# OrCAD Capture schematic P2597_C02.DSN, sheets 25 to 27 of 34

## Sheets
25 09_PCIe x4 Connector: size Custom
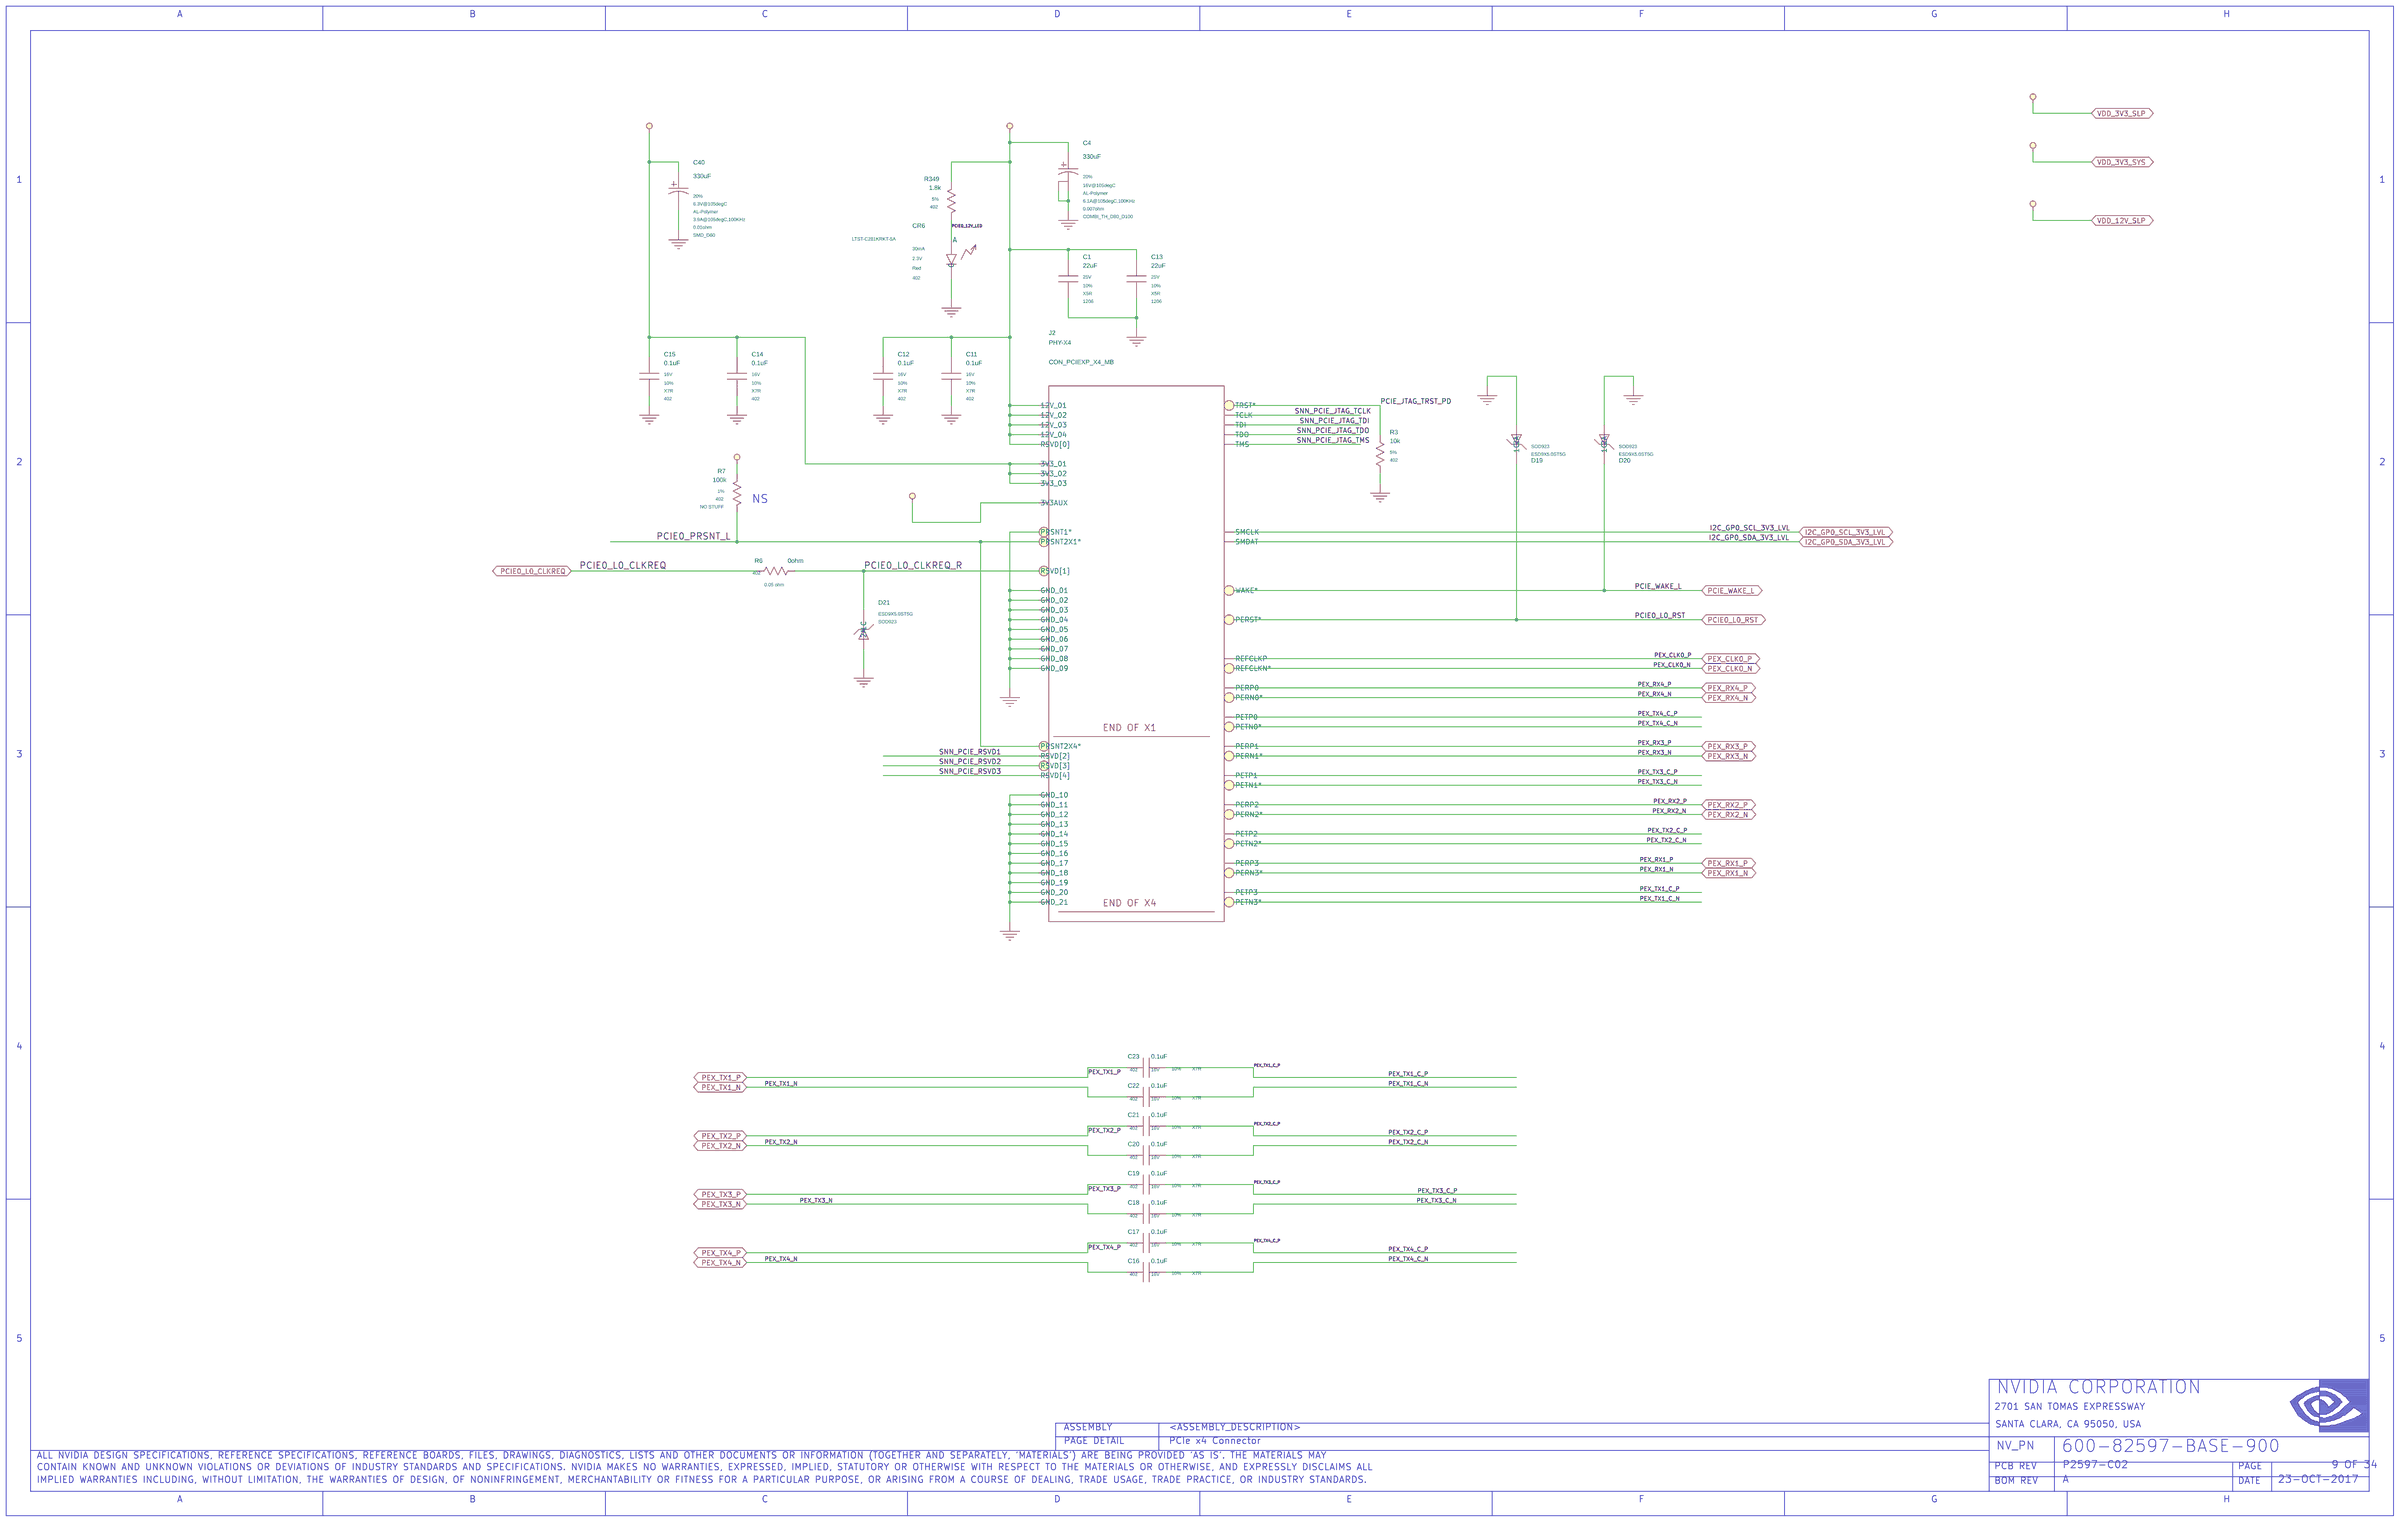
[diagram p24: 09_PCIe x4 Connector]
26 08_USB3.0 type A and USB2.0 m: size Custom
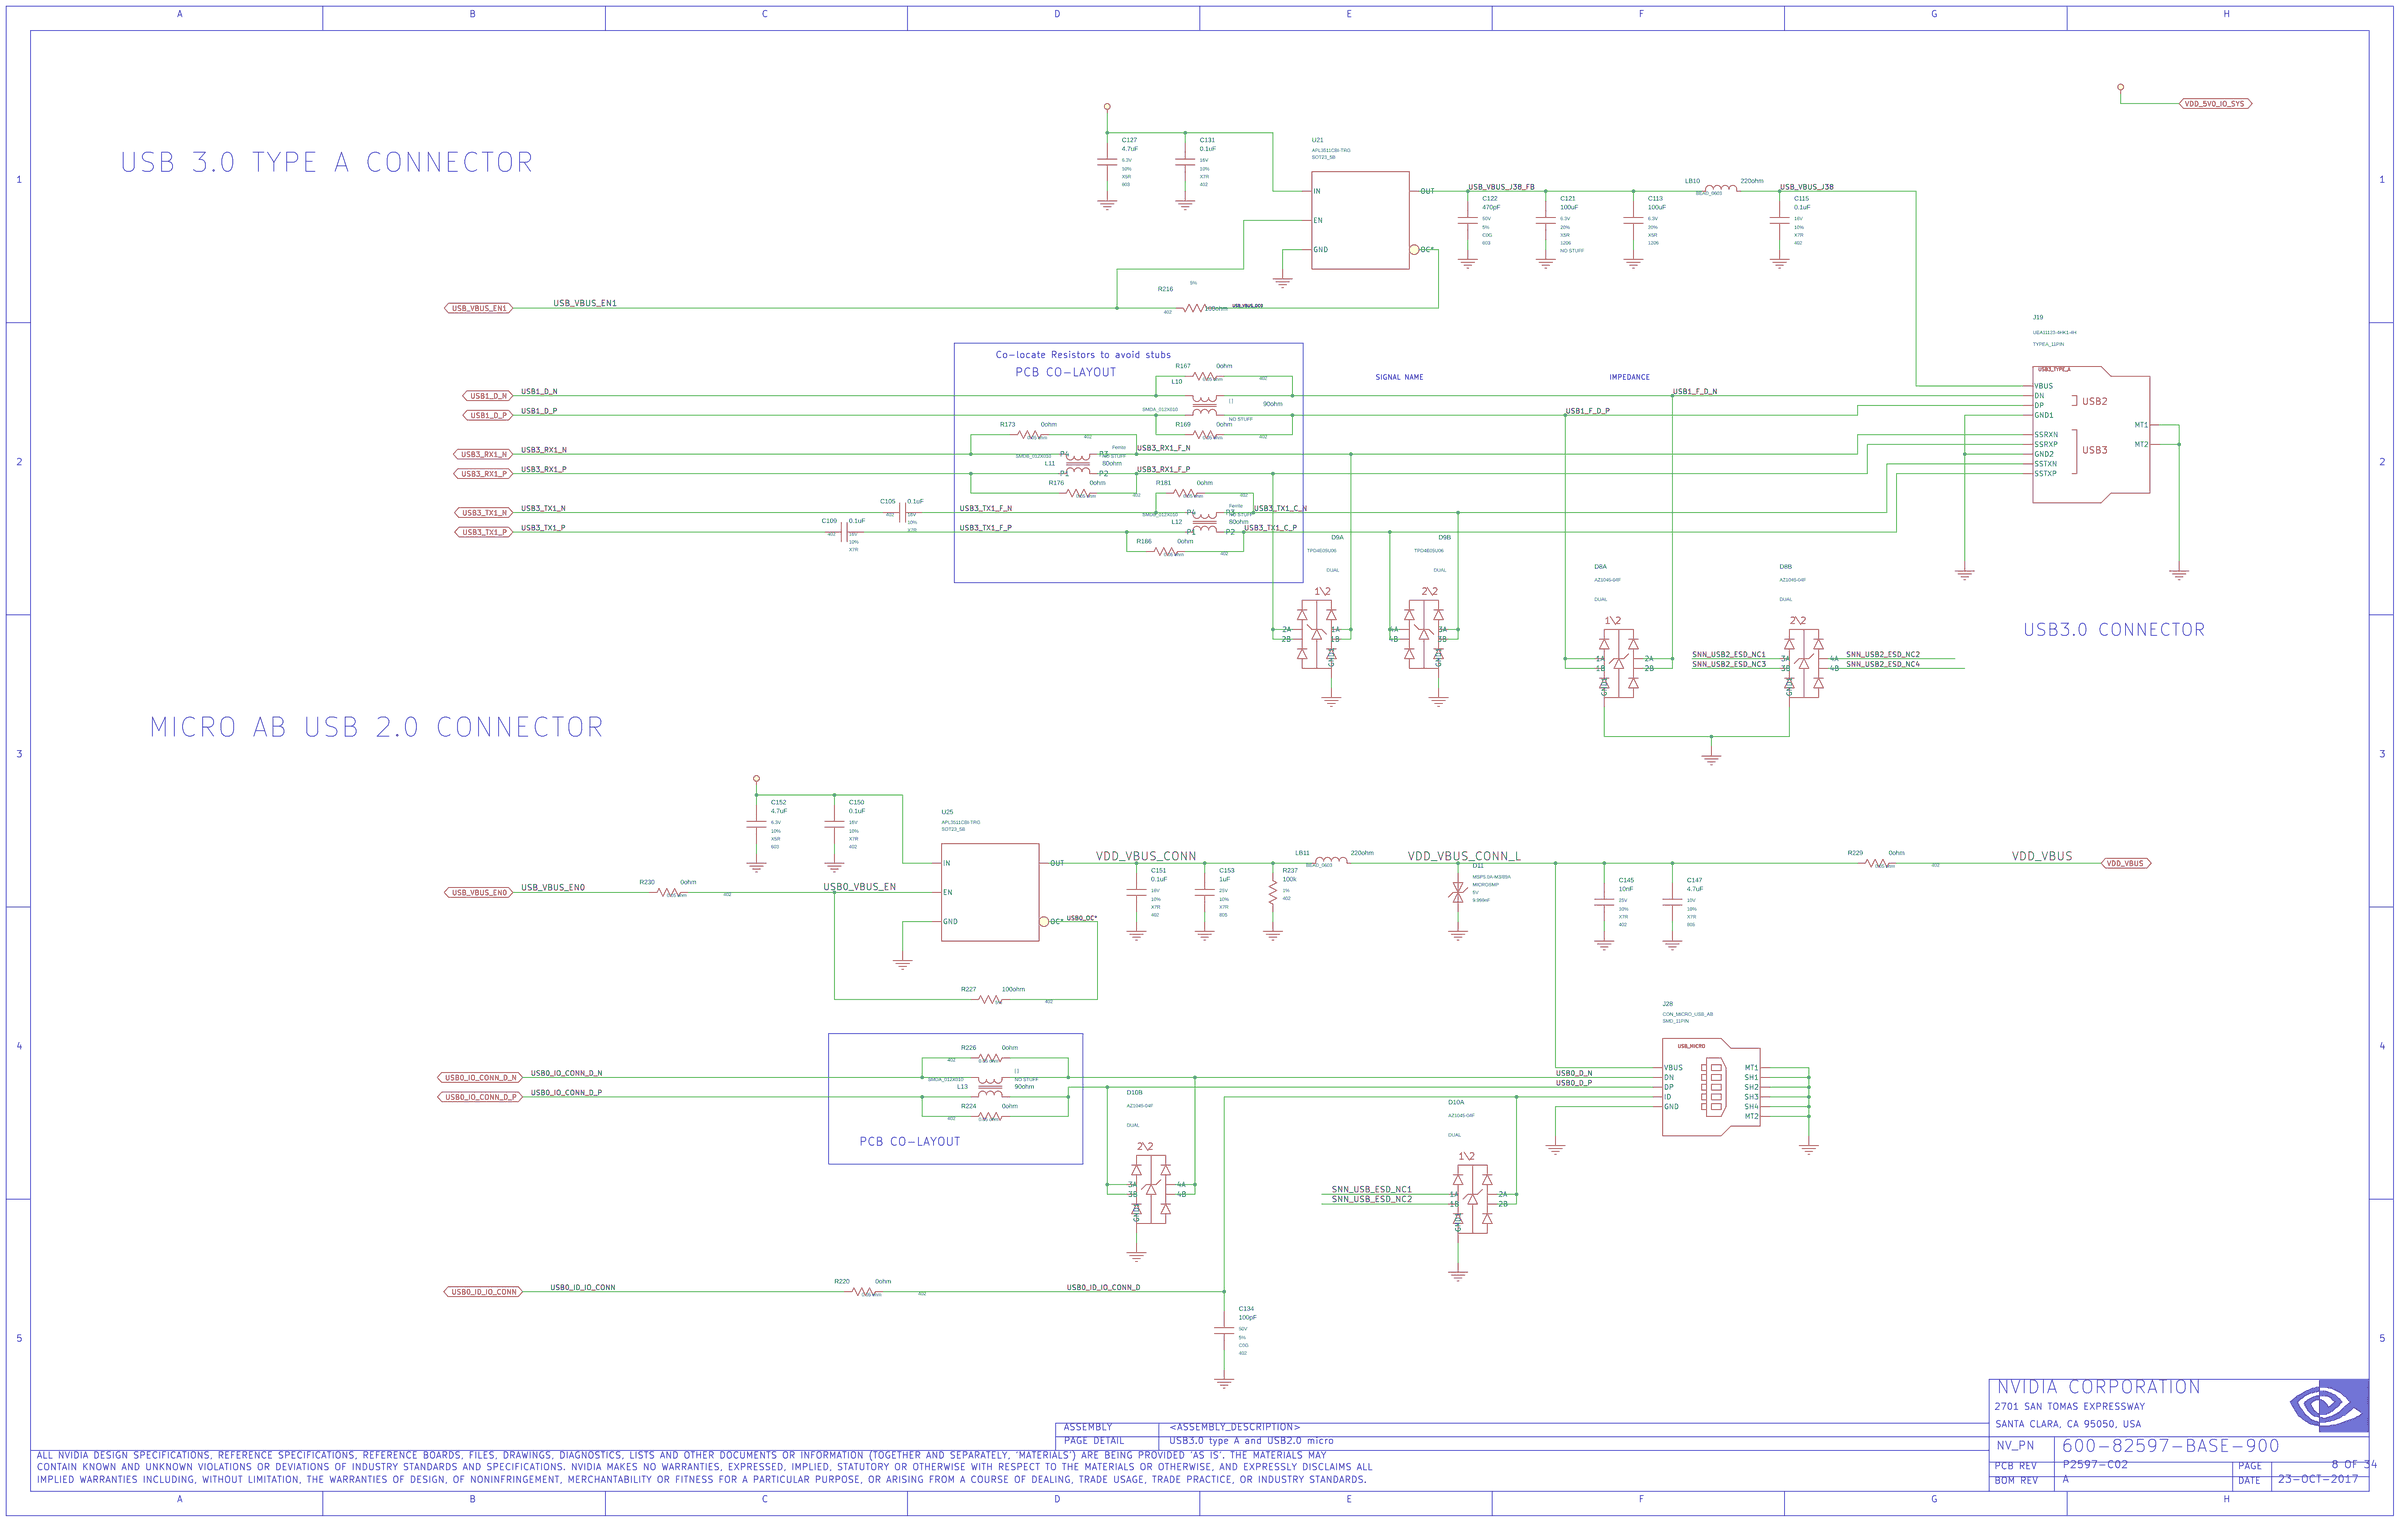
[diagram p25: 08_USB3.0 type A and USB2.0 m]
27 07_BLANK
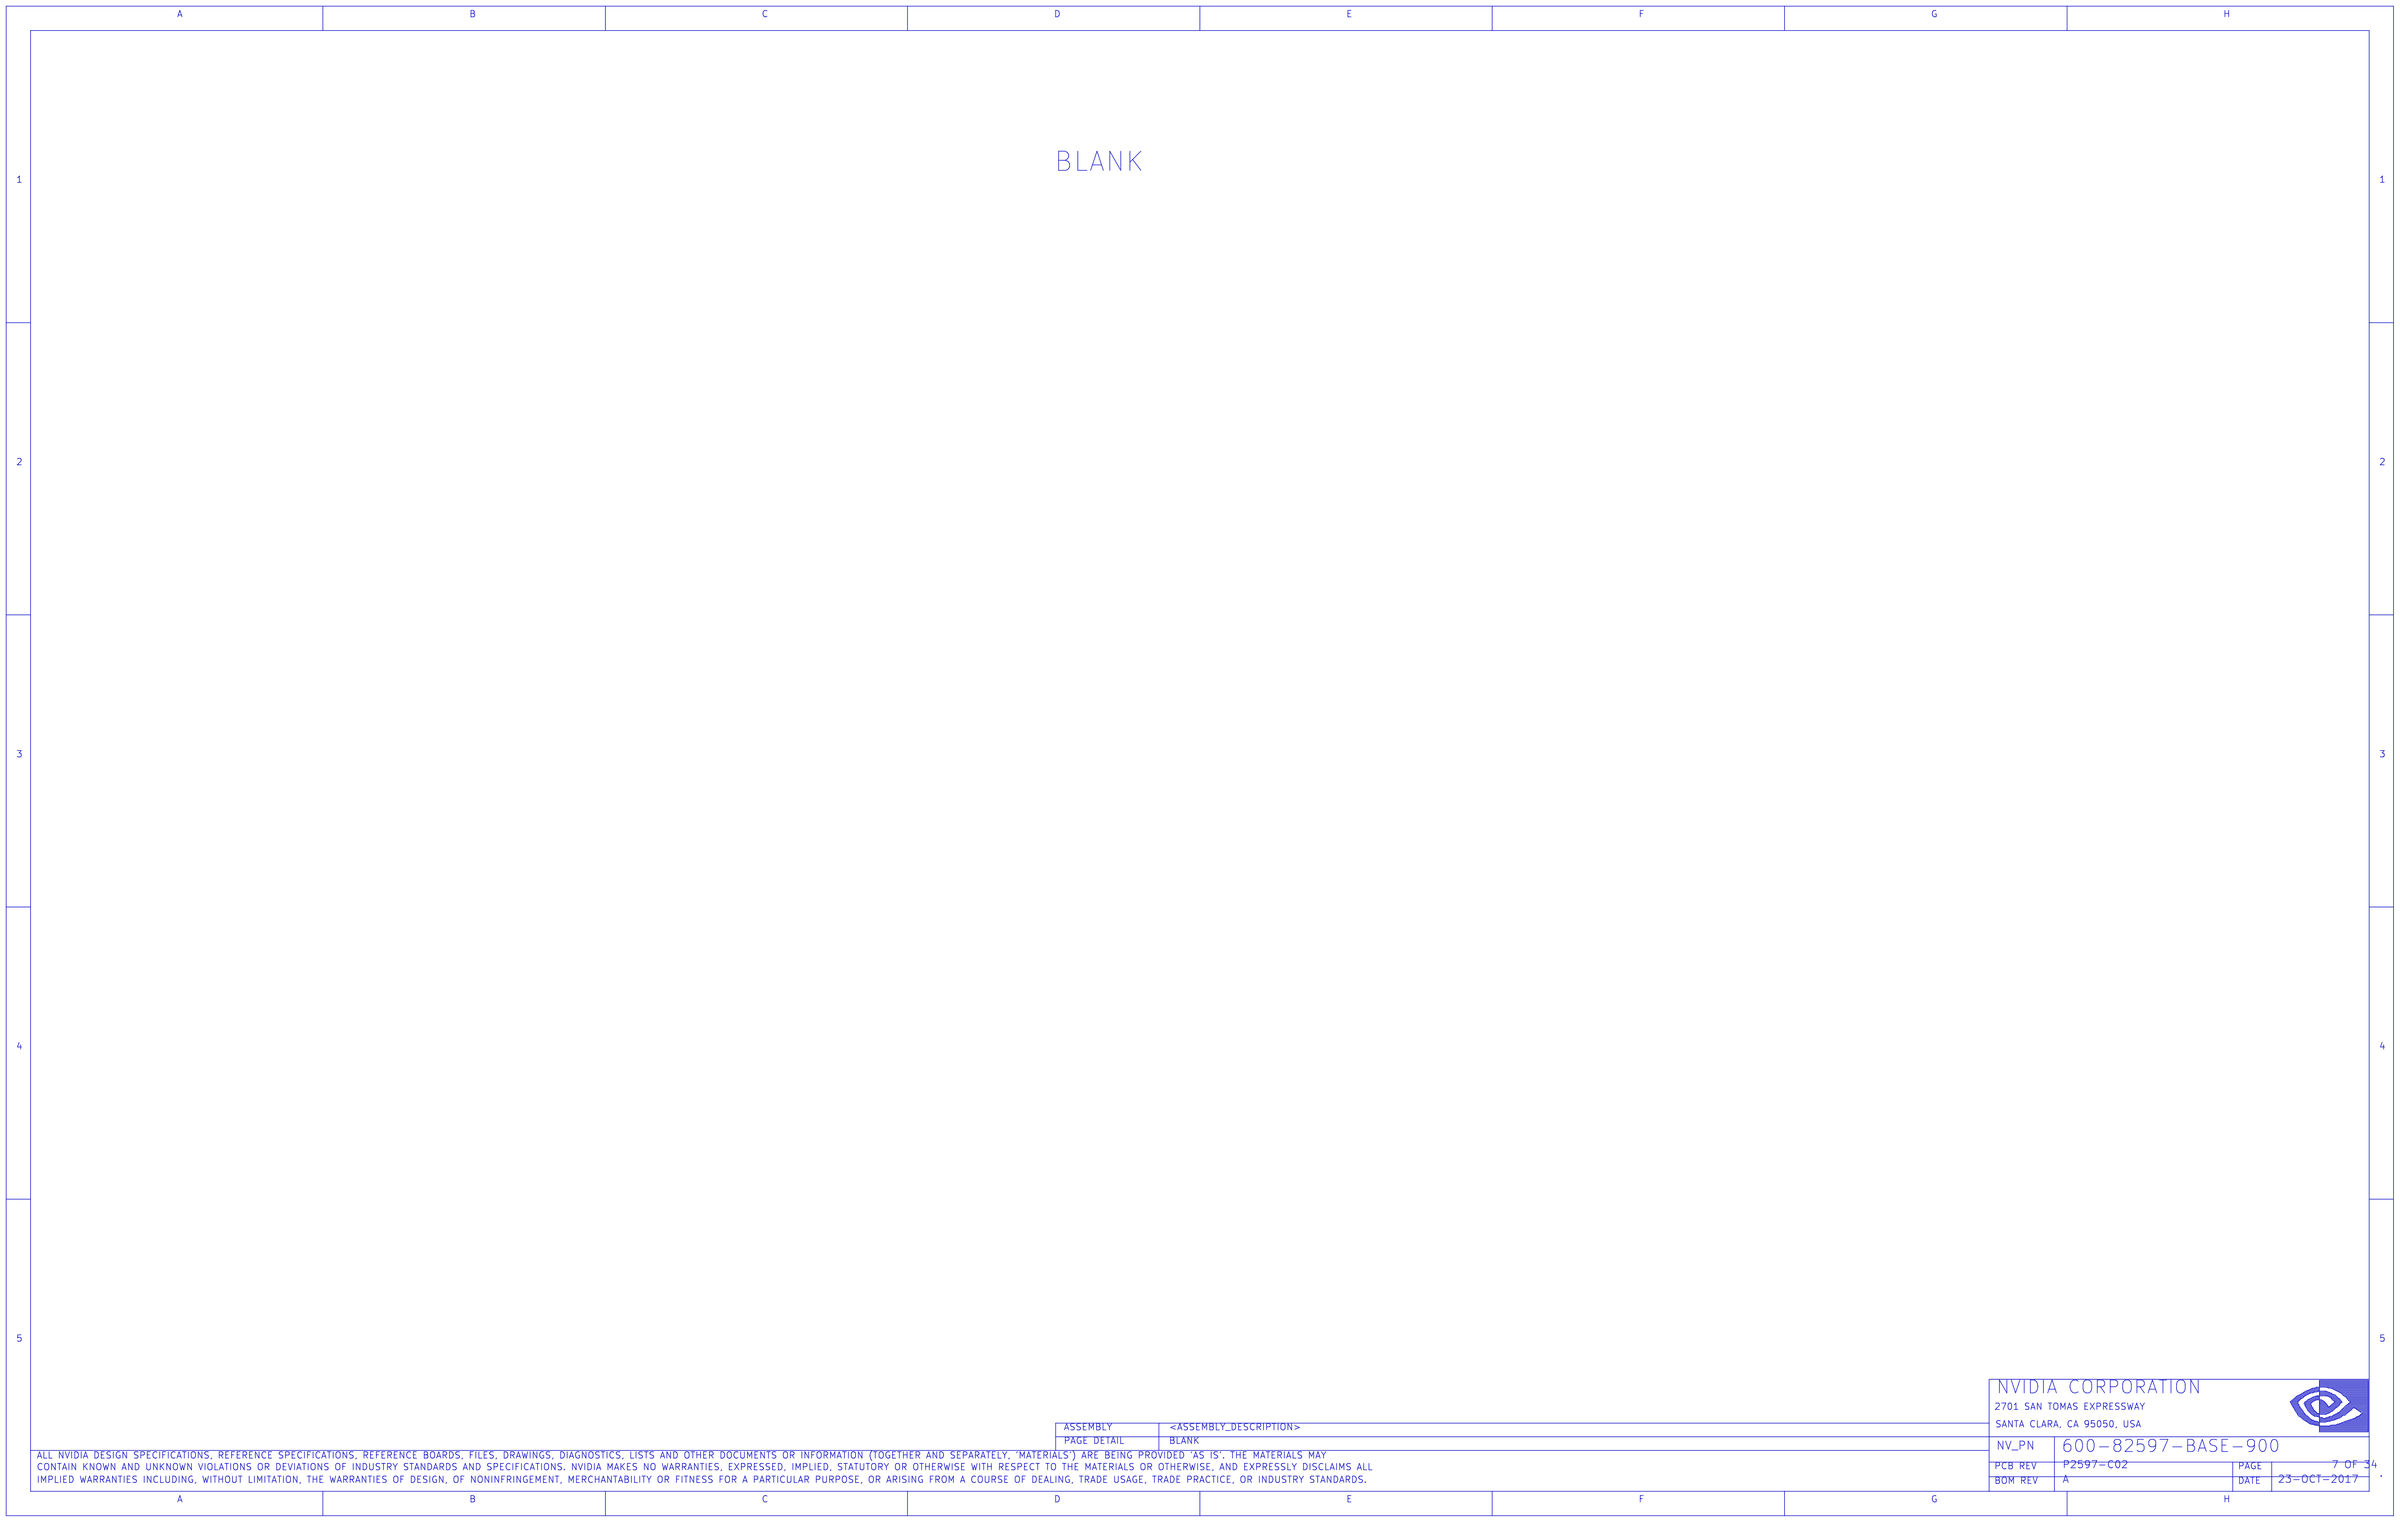
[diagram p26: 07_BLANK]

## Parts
sheet 08_USB3.0 type A and USB2.0 m
C105  0.1uF  [402]
C109  0.1uF  [402]
C113  100uF  [1206]
C115  0.1uF  [402]
C121  100uF  [1206]
C122  470pF  [603]
C127  4.7uF  [603]
C131  0.1uF  [402]
C134  100pF  [402]
C145  10nF  [402]
C147  4.7uF  [805]
C150  0.1uF  [402]
C151  0.1uF  [402]
C152  4.7uF  [603]
C153  1uF  [805]
D8  D_ESD_DIFFPAIR#1  [TSLP10_P050_025X010]  (sections A,B)
D9  D_ESD_DIFFPAIR#1  [TSLP10_P050_025X010]  (sections A,B)
D10  D_ESD_DIFFPAIR#1  [TSLP10_P050_025X010]  (sections A,B)
D11  D_ESD  [DIODE_SMD_025X013]
J19  CON_USB3  [CON_USB_009_TH_RA_138X165]
J28  CON_USB  [CON_USB_011_SMD_RA_088X058]
L10  90ohm  [IND_NONRKO_SMD_012X010]
L11  80ohm  [IND_NONRKO_SMD_012X010_B]
L12  80ohm  [IND_NONRKO_SMD_012X010_B]
L13  90ohm  [IND_NONRKO_SMD_012X010]
LB10  220ohm  [IND_SMD_0603]
LB11  220ohm  [IND_SMD_0603]
R167  0ohm  [402]
R169  0ohm  [402]
R173  0ohm  [402]
R176  0ohm  [402]
R181  0ohm  [402]
R186  0ohm  [402]
R216  100ohm  [402]
R220  0ohm  [402]
R224  0ohm  [402]
R226  0ohm  [402]
R227  100ohm  [402]
R229  0ohm  [402]
R230  0ohm  [402]
R237  100k  [402]
U21  U_POWER_SW  [SOT23_5]
U25  U_POWER_SW  [SOT23_5]
sheet 09_PCIe x4 Connector
C1  22uF  [1206]
C4  330uF  [MULTI_CAP_TH_D080P035_D100P050]
C11  0.1uF  [402]
C12  0.1uF  [402]
C13  22uF  [1206]
C14  0.1uF  [402]
C15  0.1uF  [402]
C16  0.1uF  [402]
C17  0.1uF  [402]
C18  0.1uF  [402]
C19  0.1uF  [402]
C20  0.1uF  [402]
C21  0.1uF  [402]
C22  0.1uF  [402]
C23  0.1uF  [402]
C40  330uF  [CAP_SMD_066X066]
CR6  LED  [LED_SMD_0402_ST]
D19  D_ESD  [DIODE_SMD_SOD923]
D20  D_ESD  [DIODE_SMD_SOD923]
D21  D_ESD  [DIODE_SMD_SOD923]
J2  CON_PCI_EXPRESS  [CON_PEX_064_SMT_ST]
R3  10k  [402]
R6  0ohm  [402]
R7  100k  [402]
R349  1.8k  [402]

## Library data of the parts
C105 = C#1: ASSEMBLY: USB3_TYPEA; CDS_LIB: discrete; CDS_PART_NAME: C_0402-0.1UF,X7R,10%,16V,036-0014-000; CDS_PHYS_PART_NAME: C_0402-0.1UF,X7R,10%,16V,036-0014-000-0.1UF,036-0014-000; CDS_SEC: 1; CHIPS_PART_NAME: C; DEVICE_TYPENAME: C_0402-01UFX7R1016V036-0014-000-01UF036-0014-000; DRAWING: @P2597_C02_LIB.P2597_C02(SCH_1):PAGE8; MAT: X7R; MAX_VOLTAGE: 16V; NV_PN: 036-0014-000; PATH: I213; PHYS_PAGE: 8; ROT: 0; SEC: 1; SIGNAL_MODEL: DEFAULT_CAPACITOR_100000pF_2_1; TOL: 10%; VER: 2; XY: (-7550,5000)
C109 = C#1: ASSEMBLY: USB3_TYPEA; CDS_LIB: discrete; CDS_PART_NAME: C_0402-0.1UF,X7R,10%,16V,036-0014-000; CDS_PHYS_PART_NAME: C_0402-0.1UF,X7R,10%,16V,036-0014-000-0.1UF,036-0014-000; CDS_SEC: 1; CHIPS_PART_NAME: C; DEVICE_TYPENAME: C_0402-01UFX7R1016V036-0014-000-01UF036-0014-000; DRAWING: @P2597_C02_LIB.P2597_C02(SCH_1):PAGE8; MAT: X7R; MAX_VOLTAGE: 16V; NV_PN: 036-0014-000; PATH: I212; PHYS_PAGE: 8; ROT: 0; SEC: 1; SIGNAL_MODEL: DEFAULT_CAPACITOR_100000pF_2_1; TOL: 10%; VER: 2; XY: (-7850,4900)
C113 = C: ASSEMBLY: USB3_TYPEA; CDS_LIB: discrete; CDS_PART_NAME: C_1206-100UF,X5R,20%,6.3V,039-0148-000; CDS_PHYS_PART_NAME: C_1206-100UF,X5R,20%,6.3V,039-0148-000-039-0148-000,100UF; CDS_SEC: 1; DEVICE_TYPENAME: C_1206-100UFX5R2063V039-0148-000-039-0148-000100UF; DRAWING: @P2597_C02_LIB.P2597_C02(SCH_1):PAGE8; MAT: X5R; MAX_VOLTAGE: 6.3V; NV_PN: 039-0148-000; PATH: I65; PHYS_PAGE: 8; ROT: 0; SEC: 1; SIGNAL_MODEL: DEFAULT_CAPACITOR_1e+08pF_2_1; TOL: 20%; VER: 1; XY: (-3800,6500)
C115 = C: ASSEMBLY: USB3_TYPEA; CDS_LIB: discrete; CDS_PART_NAME: C_0402-0.1UF,X7R,10%,16V,036-0014-000; CDS_PHYS_PART_NAME: C_0402-0.1UF,X7R,10%,16V,036-0014-000-0.1UF,036-0014-000; CDS_SEC: 1; DEVICE_TYPENAME: C_0402-01UFX7R1016V036-0014-000-01UF036-0014-000; DRAWING: @P2597_C02_LIB.P2597_C02(SCH_1):PAGE8; MAT: X7R; MAX_VOLTAGE: 16V; NV_PN: 036-0014-000; PATH: I74; PHYS_PAGE: 8; ROT: 0; SEC: 1; SIGNAL_MODEL: DEFAULT_CAPACITOR_100000pF_2_1; TOL: 10%; VER: 1; XY: (-3050,6500)
C121 = C: ASSEMBLY: USB3_TYPEA; CDS_LIB: discrete; CDS_PART_NAME: C_1206-100UF,X5R,20%,6.3V,039-0148-000; CDS_PHYS_PART_NAME: C_1206-100UF,X5R,20%,6.3V,039-0148-000-039-0148-000,100UF; CDS_SEC: 1; DEVICE_TYPENAME: C_1206-100UFX5R2063V039-0148-000-039-0148-000100UF; DRAWING: @P2597_C02_LIB.P2597_C02(SCH_1):PAGE8; MAT: X5R; MAX_VOLTAGE: 6.3V; NV_PN: 039-0148-000; PATH: I88; PHYS_PAGE: 8; ROT: 0; SEC: 1; SIGNAL_MODEL: DEFAULT_CAPACITOR_1e+08pF_2_1; SKU: NO STUFF; TOL: 20%; VER: 1; XY: (-4250,6500)
C122 = C: ASSEMBLY: USB3_TYPEA; CDS_LIB: discrete; CDS_PART_NAME: C_0603-470PF,C0G,5%,50V,035-0056-000; CDS_PHYS_PART_NAME: C_0603-470PF,C0G,5%,50V,035-0056-000-035-0056-000,470PF; CDS_SEC: 1; DEVICE_TYPENAME: C_0603-470PFC0G550V035-0056-000-035-0056-000470PF; DRAWING: @P2597_C02_LIB.P2597_C02(SCH_1):PAGE8; MAT: C0G; MAX_VOLTAGE: 50V; NV_PN: 035-0056-000; PATH: I90; PHYS_PAGE: 8; ROT: 0; SEC: 1; SIGNAL_MODEL: DEFAULT_CAPACITOR_470pF_2_1; TOL: 5%; VER: 1; XY: (-4650,6500)
C127 = C: ASSEMBLY: USB3_TYPEA; CDS_LIB: discrete; CDS_PART_NAME: C_0603-4.7UF,X5R,10%,6.3V,039-0037-000; CDS_PHYS_PART_NAME: C_0603-4.7UF,X5R,10%,6.3V,039-0037-000-039-0037-000,4.7UF; CDS_SEC: 1; DEVICE_TYPENAME: C_0603-47UFX5R1063V039-0037-000-039-0037-00047UF; DRAWING: @P2597_C02_LIB.P2597_C02(SCH_1):PAGE8; MAT: X5R; MAX_VOLTAGE: 6.3V; NV_PN: 039-0037-000; PATH: I82; PHYS_PAGE: 8; ROT: 0; SEC: 1; SIGNAL_MODEL: DEFAULT_CAPACITOR_4.7e+06pF_2_1; TOL: 10%; VER: 1; XY: (-6500,6800)
C131 = C: ASSEMBLY: USB3_TYPEA; CDS_LIB: discrete; CDS_PART_NAME: C_0402-0.1UF,X7R,10%,16V,036-0014-000; CDS_PHYS_PART_NAME: C_0402-0.1UF,X7R,10%,16V,036-0014-000-0.1UF,036-0014-000; CDS_SEC: 1; DEVICE_TYPENAME: C_0402-01UFX7R1016V036-0014-000-01UF036-0014-000; DRAWING: @P2597_C02_LIB.P2597_C02(SCH_1):PAGE8; MAT: X7R; MAX_VOLTAGE: 16V; NV_PN: 036-0014-000; PATH: I84; PHYS_PAGE: 8; ROT: 0; SEC: 1; SIGNAL_MODEL: DEFAULT_CAPACITOR_100000pF_2_1; TOL: 10%; VER: 1; XY: (-6100,6800)
C134 = C: ASSEMBLY: MICRO_USB; CDS_LIB: discrete; CDS_PART_NAME: C_0402-100PF,C0G,5%,50V,035-0012-000; CDS_PHYS_PART_NAME: C_0402-100PF,C0G,5%,50V,035-0012-000-035-0012-000,100PF; CDS_SEC: 1; DEVICE_TYPENAME: C_0402-100PFC0G550V035-0012-000-035-0012-000100PF; DRAWING: @P2597_C02_LIB.P2597_C02(SCH_1):PAGE8; ESL: N/A; ESR: N/A; MAT: C0G; MAX_VOLTAGE: 50V; NV_PN: 035-0012-000; PATH: I148; PHYS_PAGE: 8; ROT: 0; SEC: 1; SIGNAL_MODEL: nv_cap; TOL: 5%; VER: 1; XY: (-5900,800)
C145 = C: ASSEMBLY: MICRO_USB; CDS_LIB: discrete; CDS_PART_NAME: C_0402-10NF,X7R,10%,25V,036-0019-000; CDS_PHYS_PART_NAME: C_0402-10NF,X7R,10%,25V,036-0019-000-036-0019-000,10NF; CDS_SEC: 1; DEVICE_TYPENAME: C_0402-10NFX7R1025V036-0019-000-036-0019-00010NF; DRAWING: @P2597_C02_LIB.P2597_C02(SCH_1):PAGE8; MAT: X7R; MAX_VOLTAGE: 25V; NV_PN: 036-0019-000; PATH: I158; PHYS_PAGE: 8; ROT: 0; SEC: 1; SIGNAL_MODEL: DEFAULT_CAPACITOR_10000pF_2_1; TOL: 10%; VER: 1; XY: (-3950,3000)
C147 = C: ASSEMBLY: MICRO_USB; CDS_LIB: discrete; CDS_PART_NAME: C_0805-4.7UF,X7R,10%,10V,036-0128-000; CDS_PHYS_PART_NAME: C_0805-4.7UF,X7R,10%,10V,036-0128-000-036-0128-000,4.7UF; CDS_SEC: 1; DEVICE_TYPENAME: C_0805-47UFX7R1010V036-0128-000-036-0128-00047UF; DRAWING: @P2597_C02_LIB.P2597_C02(SCH_1):PAGE8; MAT: X7R; MAX_VOLTAGE: 10V; NV_PN: 036-0128-000; PATH: I162; PHYS_PAGE: 8; ROT: 0; SEC: 1; SIGNAL_MODEL: nv_cap; TOL: 10%; VER: 1; XY: (-3600,3000)
C150 = C: ASSEMBLY: MICRO_USB; CDS_LIB: discrete; CDS_PART_NAME: C_0402-0.1UF,X7R,10%,16V,036-0014-000; CDS_PHYS_PART_NAME: C_0402-0.1UF,X7R,10%,16V,036-0014-000-0.1UF,036-0014-000; CDS_SEC: 1; DEVICE_TYPENAME: C_0402-01UFX7R1016V036-0014-000-01UF036-0014-000; DRAWING: @P2597_C02_LIB.P2597_C02(SCH_1):PAGE8; MAT: X7R; MAX_VOLTAGE: 16V; NV_PN: 036-0014-000; PATH: I174; PHYS_PAGE: 8; ROT: 0; SEC: 1; SIGNAL_MODEL: DEFAULT_CAPACITOR_100000pF_2_1; TOL: 10%; VER: 1; XY: (-7900,3400)
C151 = C: ASSEMBLY: MICRO_USB; CDS_LIB: discrete; CDS_PART_NAME: C_0402-0.1UF,X7R,10%,16V,036-0014-000; CDS_PHYS_PART_NAME: C_0402-0.1UF,X7R,10%,16V,036-0014-000-0.1UF,036-0014-000; CDS_SEC: 1; DEVICE_TYPENAME: C_0402-01UFX7R1016V036-0014-000-01UF036-0014-000; DRAWING: @P2597_C02_LIB.P2597_C02(SCH_1):PAGE8; MAT: X7R; MAX_VOLTAGE: 16V; NV_PN: 036-0014-000; PATH: I182; PHYS_PAGE: 8; ROT: 0; SEC: 1; SIGNAL_MODEL: nv_cap; TOL: 10%; VER: 1; XY: (-6350,3050)
C152 = C: ASSEMBLY: MICRO_USB; CDS_LIB: discrete; CDS_PART_NAME: C_0603-4.7UF,X5R,10%,6.3V,039-0037-000; CDS_PHYS_PART_NAME: C_0603-4.7UF,X5R,10%,6.3V,039-0037-000-039-0037-000,4.7UF; CDS_SEC: 1; DEVICE_TYPENAME: C_0603-47UFX5R1063V039-0037-000-039-0037-00047UF; DRAWING: @P2597_C02_LIB.P2597_C02(SCH_1):PAGE8; MAT: X5R; MAX_VOLTAGE: 6.3V; NV_PN: 039-0037-000; PATH: I175; PHYS_PAGE: 8; ROT: 0; SEC: 1; SIGNAL_MODEL: DEFAULT_CAPACITOR_4.7e+06pF_2_1; TOL: 10%; VER: 1; XY: (-8300,3400)
C153 = C: ASSEMBLY: MICRO_USB; CDS_LIB: discrete; CDS_PART_NAME: C_0805-1UF,X7R,10%,25V,036-0117-000; CDS_PHYS_PART_NAME: C_0805-1UF,X7R,10%,25V,036-0117-000-036-0117-000,1UF; CDS_SEC: 1; DEVICE_TYPENAME: C_0805-1UFX7R1025V036-0117-000-036-0117-0001UF; DRAWING: @P2597_C02_LIB.P2597_C02(SCH_1):PAGE8; MAT: X7R; MAX_VOLTAGE: 25V; NV_PN: 036-0117-000; PATH: I184; PHYS_PAGE: 8; ROT: 0; SEC: 1; SIGNAL_MODEL: nv_cap; TOL: 10%; VER: 1; XY: (-6000,3050)
D8 = D_ESD_DIFFPAIR#1: ASSEMBLY: USB3_TYPEA; BREAKDOWN_VOLTAGE_MIN_TYP: 6V; CAPACITANCE_MAX_TYP: 0.65pF; CDS_LIB: discrete; CDS_PART_NAME: D_ESD_DIFFPAIR_DUAL-AZ1045-04F,2 DIFFPAIR,UNI-DIRECTIONAL,5V,1.5UA,6V,12V@3.5A,0.65PF,091-0054-000; CDS_PHYS_PART_NAME: D_ESD_DIFFPAIR_DUAL-AZ1045-04F,2 DIFFPAIR,UNI-DIRECTIONAL,5V,1.5UA,6V,12V@3.5A,0.65PF,091-0054-000-091-0054-000; CDS_SEC: 2; CHIPS_PART_NAME: D_ESD_DIFFPAIR; CLAMPING_VOLTAGE: 12V@3.5A; CONFIGURATION: 2 Diffpair; CaptureCellPackProp: D_ESD_DIFFPAIR#1B; DEVICE_TYPENAME: D_ESD_DIFFPAIR_DUAL-AZ1045-04F2DIFFPAIRUNI-DIRECTIONAL5V15UA6V12V35A065PF091-0054-000-091-0054-000; DRAWING: @P2597_C02_LIB.P2597_C02(SCH_1):PAGE8; MAX_REVERSE_LEAKAGE_CURRENT: 1.5uA; MAX_REVERSE_VOLTAGE: 5V; NV_NAME: AZ1045-04F; NV_PN: 091-0054-000; PACK_TYPE: DUAL; PATH: I217; PHYS_PAGE: 8; POLARITY: Uni-Directional; ROT: 0; SEC: 2; SEC_TYPE: DUAL; VER: 2; XY: (-2950,4250)
D9 = D_ESD_DIFFPAIR#1: ASSEMBLY: USB3_TYPEA; BREAKDOWN_VOLTAGE_MIN_TYP: 6V; CAPACITANCE_MAX_TYP: 0.5pF; CDS_LIB: discrete; CDS_PART_NAME: D_ESD_DIFFPAIR_DUAL-TPD4E05U06,2 DIFFPAIR,UNI-DIRECTIONAL,5.5V,10UA,6V,10V@1A,0.5PF,090-0231-000; CDS_PHYS_PART_NAME: D_ESD_DIFFPAIR_DUAL-TPD4E05U06,2 DIFFPAIR,UNI-DIRECTIONAL,5.5V,10UA,6V,10V@1A,0.5PF,090-0231-000-090-0231-000; CDS_SEC: 1; CHIPS_PART_NAME: D_ESD_DIFFPAIR; CLAMPING_VOLTAGE: 10V@1A; CONFIGURATION: 2 Diffpair; CaptureCellPackProp: D_ESD_DIFFPAIR#1A; DEVICE_TYPENAME: D_ESD_DIFFPAIR_DUAL-TPD4E05U062DIFFPAIRUNI-DIRECTIONAL55V10UA6V10V1A05PF090-0231-000-090-0231-000; DRAWING: @P2597_C02_LIB.P2597_C02(SCH_1):PAGE8; MAX_REVERSE_LEAKAGE_CURRENT: 10uA; MAX_REVERSE_VOLTAGE: 5.5V; NV_NAME: TPD4E05U06; NV_PN: 090-0231-000; PACK_TYPE: DUAL; PATH: I62; PHYS_PAGE: 8; POLARITY: Uni-Directional; ROT: 2; SEC: 1; VER: 1; XY: (-5400,4400)
D10 = D_ESD_DIFFPAIR#1: ASSEMBLY: MICRO_USB; BREAKDOWN_VOLTAGE_MIN_TYP: 6V; CAPACITANCE_MAX_TYP: 0.65pF; CDS_LIB: discrete; CDS_PART_NAME: D_ESD_DIFFPAIR_DUAL-AZ1045-04F,2 DIFFPAIR,UNI-DIRECTIONAL,5V,1.5UA,6V,12V@3.5A,0.65PF,091-0054-000; CDS_PHYS_PART_NAME: D_ESD_DIFFPAIR_DUAL-AZ1045-04F,2 DIFFPAIR,UNI-DIRECTIONAL,5V,1.5UA,6V,12V@3.5A,0.65PF,091-0054-000-091-0054-000; CDS_SEC: 1; CHIPS_PART_NAME: D_ESD_DIFFPAIR; CLAMPING_VOLTAGE: 12V@3.5A; CONFIGURATION: 2 Diffpair; CaptureCellPackProp: D_ESD_DIFFPAIR#1A; DEVICE_TYPENAME: D_ESD_DIFFPAIR_DUAL-AZ1045-04F2DIFFPAIRUNI-DIRECTIONAL5V15UA6V12V35A065PF091-0054-000-091-0054-000; DRAWING: @P2597_C02_LIB.P2597_C02(SCH_1):PAGE8; MAX_REVERSE_LEAKAGE_CURRENT: 1.5uA; MAX_REVERSE_VOLTAGE: 5V; NV_NAME: AZ1045-04F; NV_PN: 091-0054-000; PACK_TYPE: DUAL; PATH: I155; PHYS_PAGE: 8; POLARITY: Uni-Directional; ROT: 0; SEC: 1; SEC_TYPE: DUAL; VER: 1; XY: (-4650,1500)
D11 = D_ESD: ASSEMBLY: MICRO_USB; BREAKDOWN_VOLTAGE_MIN_TYP: 6.4V; CAPACITANCE_MAX_TYP: 9.999nF; CDS_LIB: discrete; CDS_PART_NAME: D_ESD_MICROSMP-MSP5.0A-M3/89A,1 LINE,UNI-DIRECTIONAL,5V,100UA,6.4V,9.2V@16.3A,9.999NF,090-0233-000; CDS_PHYS_PART_NAME: D_ESD_MICROSMP-MSP5.0A-M3/89A,1 LINE,UNI-DIRECTIONAL,5V,100UA,6.4V,9.2V@16.3A,9.999NF,090-0233-000-090-0233-000; CDS_SEC: 1; CLAMPING_VOLTAGE: 9.2V@16.3A; CONFIGURATION: 1 Line; DEVICE_TYPENAME: D_ESD_MICROSMP-MSP50A-M389A1LINEUNI-DIRECTIONAL5V100UA64V92V163A9999NF090-0233-000-090-0233-000; DRAWING: @P2597_C02_LIB.P2597_C02(SCH_1):PAGE8; MAX_REVERSE_LEAKAGE_CURRENT: 100uA; MAX_REVERSE_VOLTAGE: 5V; NV_NAME: MSP5.0A-M3/89A; NV_PN: 090-0233-000; PACK_TYPE: MICROSMP; PATH: I189; PHYS_PAGE: 8; POLARITY: Uni-Directional; ROT: 0; SEC: 1; SEC_TYPE: MICROSMP; VER: 2; XY: (-4700,3050)
J19 = CON_USB3: ANGLE: 90; ASSEMBLY: USB3_TYPEA; CDS_LIB: electro_mechanic; CDS_PART_NAME: CON_USB3_TYPEA_11PIN-UEA11123-4HK1-4H,FEMALE,2MM,90,YES,NO,YES,NO,YES,5V,0.5A,065-0399-000; CDS_PHYS_PART_NAME: CON_USB3_TYPEA_11PIN-UEA11123-4HK1-4H,FEMALE,2MM,90,YES,NO,YES,NO,YES,5V,0.5A,065-0399-000-065-0399-000; CDS_SEC: 1; DEVICE_TYPENAME: CON_USB3_TYPEA_11PIN-UEA11123-4HK1-4HFEMALE2MM90YESNOYESNOYES5V05A065-0399-000-065-0399-000; DRAWING: @P2597_C02_LIB.P2597_C02(SCH_1):PAGE8; EMI_GROUND_TAB: NO; GENDER: Female; LATCHING: YES; MAX_CURRENT: 0.5A; MAX_VOLTAGE: 5V; NV_NAME: UEA11123-4HK1-4H; NV_PN: 065-0399-000; PACK_TYPE: TYPEA_11PIN; PATH: I143; PHYS_PAGE: 8; PITCH: 2mm; REFLOW: YES; ROT: 0; SEC: 1; SEC_TYPE: TYPEA_11PIN; SHIELDED: YES; SHROUDED: No; VER: 1; XY: (-1450,5400)
J28 = CON_USB: ANGLE: 90; ASSEMBLY: MICRO_USB; CDS_LIB: electro_mechanic; CDS_PART_NAME: CON_USB_SMD_11PIN-CON_MICRO_USB_AB,RECEPTACLE,.65MM,90,YES,YES,NO,YES,YES,500VAC,1A,080-0280-000; CDS_PHYS_PART_NAME: CON_USB_SMD_11PIN-CON_MICRO_USB_AB,RECEPTACLE,.65MM,90,YES,YES,NO,YES,YES,500VAC,1A,080-0280-000-080-0280-000; CDS_SEC: 1; DEVICE_TYPENAME: CON_USB_SMD_11PIN-CON_MICRO_USB_ABRECEPTACLE65MM90YESYESNOYESYES500VAC1A080-0280-000-080-0280-000; DRAWING: @P2597_C02_LIB.P2597_C02(SCH_1):PAGE8; EMI_GROUND_TAB: YES; GENDER: RECEPTACLE; LATCHING: NO; MAX_CURRENT: 1A; MAX_VOLTAGE: 500VAC; NV_NAME: CON_MICRO_USB_AB; NV_PN: 080-0280-000; PACK_TYPE: SMD_11PIN; PATH: I210; PHYS_PAGE: 8; PITCH: .65MM; REFLOW: YES; ROT: 0; SEC: 1; SHIELDED: YES; SHROUDED: YES; VER: 4; XY: (-3400,2050)
L10 = L_CMF_4P#2: ASSEMBLY: USB3_TYPEA; CDS_LIB: discrete; CDS_PART_NAME: L_CMF_4P_SMDA_012X010-90OHM,[ ],25%,0.2A,0.4OHM,[ ],102-0037-000; CDS_PHYS_PART_NAME: L_CMF_4P_SMDA_012X010-90OHM,[ ],25%,0.2A,0.4OHM,[ ],102-0037-000-102-0037-000,90OHM; CDS_SEC: 1; CHIPS_PART_NAME: L_CMF_4P; DC_RESISTANCE: 0.4ohm; DEVICE_TYPENAME: L_CMF_4P_SMDA_012X010-90OHM2502A04OHM102-0037-000-102-0037-00090OHM; DRAWING: @P2597_C02_LIB.P2597_C02(SCH_1):PAGE8; MAT: [ ]; MAX_CURRENT: 0.2A; NV_NAME: [ ]; NV_PN: 102-0037-000; PACK_TYPE: SMDA_012X010; PATH: I191; PHYS_PAGE: 8; PLACEMENT_NOTE: CoLayout with R167, R169; ROT: 6; SEC: 1; SEC_TYPE: SMDA_012X010; SIGNAL_MODEL: nv_ind_cmf_4p; SKU: NO STUFF; TOL: 25%; VER: 3; XY: (-6000,5550)
L11 = L_CMF_4P#1: ASSEMBLY: USB3_TYPEA; CDS_LIB: discrete; CDS_PART_NAME: L_CMF_4P_SMDB_012X010-80OHM,FERRITE,25%,0.1A,1.5OHM,DLP11TB800UL2,102-0023-000; CDS_PHYS_PART_NAME: L_CMF_4P_SMDB_012X010-80OHM,FERRITE,25%,0.1A,1.5OHM,DLP11TB800UL2,102-0023-000-102-0023-000,80OHM; CDS_SEC: 1; CHIPS_PART_NAME: L_CMF_4P; DC_RESISTANCE: 1.5ohm; DEVICE_TYPENAME: L_CMF_4P_SMDB_012X010-80OHMFERRITE2501A15OHMDLP11TB800UL2102-0023-000-102-0023-00080OHM; DRAWING: @P2597_C02_LIB.P2597_C02(SCH_1):PAGE8; MAT: Ferrite; MAX_CURRENT: 0.1A; NV_NAME: DLP11TB800UL2; NV_PN: 102-0023-000; PACK_TYPE: SMDB_012X010; PATH: I56; PHYS_PAGE: 8; PLACEMENT_NOTE: CoLayout with R173, R176; ROT: 6; SEC: 1; SEC_TYPE: SMDB_012X010; SIGNAL_MODEL: nv_ind_cmf_4p_0504; SKU: NO STUFF; TOL: 25%; VER: 5; XY: (-6650,5250)
L12 = L_CMF_4P#1: ASSEMBLY: USB3_TYPEA; CDS_LIB: discrete; CDS_PART_NAME: L_CMF_4P_SMDB_012X010-80OHM,FERRITE,25%,0.1A,1.5OHM,DLP11TB800UL2,102-0023-000; CDS_PHYS_PART_NAME: L_CMF_4P_SMDB_012X010-80OHM,FERRITE,25%,0.1A,1.5OHM,DLP11TB800UL2,102-0023-000-102-0023-000,80OHM; CDS_SEC: 1; CHIPS_PART_NAME: L_CMF_4P; DC_RESISTANCE: 1.5ohm; DEVICE_TYPENAME: L_CMF_4P_SMDB_012X010-80OHMFERRITE2501A15OHMDLP11TB800UL2102-0023-000-102-0023-00080OHM; DRAWING: @P2597_C02_LIB.P2597_C02(SCH_1):PAGE8; MAT: Ferrite; MAX_CURRENT: 0.1A; NV_NAME: DLP11TB800UL2; NV_PN: 102-0023-000; PACK_TYPE: SMDB_012X010; PATH: I54; PHYS_PAGE: 8; PLACEMENT_NOTE: CoLayout with R181, R186; ROT: 6; SEC: 1; SEC_TYPE: SMDB_012X010; SIGNAL_MODEL: nv_ind_cmf_4p_0504; SKU: NO STUFF; TOL: 25%; VER: 5; XY: (-6000,4950)
L13 = L_CMF_4P: ASSEMBLY: MICRO_USB; CDS_LIB: discrete; CDS_PART_NAME: L_CMF_4P_SMDA_012X010-90OHM,[ ],25%,0.2A,0.4OHM,[ ],102-0037-000; CDS_PHYS_PART_NAME: L_CMF_4P_SMDA_012X010-90OHM,[ ],25%,0.2A,0.4OHM,[ ],102-0037-000-102-0037-000,90OHM; CDS_SEC: 1; DC_RESISTANCE: 0.4ohm; DEVICE_TYPENAME: L_CMF_4P_SMDA_012X010-90OHM2502A04OHM102-0037-000-102-0037-00090OHM; DRAWING: @P2597_C02_LIB.P2597_C02(SCH_1):PAGE8; MAT: [ ]; MAX_CURRENT: 0.2A; NO_XNET_CONNECTION: 1; NV_NAME: [ ]; NV_PN: 102-0037-000; PACK_TYPE: SMDA_012X010; PATH: I192; PHYS_PAGE: 8; PLACEMENT_NOTE: CoLayout with R226, R224; ROT: 6; SEC: 1; SEC_TYPE: SMDA_012X010; SIGNAL_MODEL: nv_ind_cmf_4p; SKU: NO STUFF; TOL: 25%; VER: 1; XY: (-7100,2050)
LB10 = L: ACOUSTIC_MARGIN: N/A; ASSEMBLY: USB3_TYPEA; CDS_LIB: discrete; CDS_PART_NAME: L_BEAD_0603-220OHM,FERRITE,25%,[ ],2.5A,0.05OHM,[ ],N/A,N/A,100-0160-000; CDS_PHYS_PART_NAME: L_BEAD_0603-220OHM,FERRITE,25%,[ ],2.5A,0.05OHM,[ ],N/A,N/A,100-0160-000-100-0160-000,220OHM; CDS_SEC: 1; CONTINUOUS_CURRENT: [ ]; DC_RESISTANCE: 0.05ohm; DEVICE_TYPENAME: L_BEAD_0603-220OHMFERRITE2525A005OHMNANA100-0160-000-100-0160-000220OHM; DRAWING: @P2597_C02_LIB.P2597_C02(SCH_1):PAGE8; MAT: Ferrite; MAX_CURRENT: 2.5A; NV_PN: 100-0160-000; PACK_TYPE: BEAD_0603; PATH: I77; PHYS_PAGE: 8; Q: [ ]; ROT: 0; SEC: 1; SELF_RESONANCE_FREQ: N/A; SIGNAL_MODEL: nv_ind_noxnet; TOL: 25%; VER: 1; XY: (-3350,6650)
LB11 = L: ACOUSTIC_MARGIN: N/A; ASSEMBLY: MICRO_USB; CDS_LIB: discrete; CDS_PART_NAME: L_BEAD_0603-220OHM,FERRITE,25%,[ ],2.5A,0.05OHM,[ ],N/A,N/A,100-0160-000; CDS_PHYS_PART_NAME: L_BEAD_0603-220OHM,FERRITE,25%,[ ],2.5A,0.05OHM,[ ],N/A,N/A,100-0160-000-100-0160-000,220OHM; CDS_SEC: 1; CONTINUOUS_CURRENT: [ ]; DC_RESISTANCE: 0.05ohm; DEVICE_TYPENAME: L_BEAD_0603-220OHMFERRITE2525A005OHMNANA100-0160-000-100-0160-000220OHM; DRAWING: @P2597_C02_LIB.P2597_C02(SCH_1):PAGE8; MAT: Ferrite; MAX_CURRENT: 2.5A; NV_PN: 100-0160-000; PACK_TYPE: BEAD_0603; PATH: I179; PHYS_PAGE: 8; Q: [ ]; ROT: 0; SEC: 1; SELF_RESONANCE_FREQ: N/A; SIGNAL_MODEL: nv_ind_noxnet; TOL: 25%; VER: 1; XY: (-5350,3200)
R167 = R: ASSEMBLY: USB3_TYPEA; CDS_LIB: discrete; CDS_PART_NAME: R_0402-0OHM,0.05 OHM,62.5MW,195-2655-000; CDS_PHYS_PART_NAME: R_0402-0OHM,0.05 OHM,62.5MW,195-2655-000-0OHM,195-2655-000; CDS_SEC: 1; DEVICE_TYPENAME: R_0402-0OHM005OHM625MW195-2655-000-0OHM195-2655-000; DRAWING: @P2597_C02_LIB.P2597_C02(SCH_1):PAGE8; MAX_WATTAGE: 62.5mW; NV_PN: 195-2655-000; PATH: I59; PHYS_PAGE: 8; PLACEMENT_NOTE: CoLayout with L10; ROT: 0; SEC: 1; SIGNAL_MODEL: DEFAULT_RESISTOR_0.001OHM_2_1; TOL: 0.05 ohm; VER: 1; XY: (-6000,5700)
R169 = R: ASSEMBLY: USB3_TYPEA; CDS_LIB: discrete; CDS_PART_NAME: R_0402-0OHM,0.05 OHM,62.5MW,195-2655-000; CDS_PHYS_PART_NAME: R_0402-0OHM,0.05 OHM,62.5MW,195-2655-000-0OHM,195-2655-000; CDS_SEC: 1; DEVICE_TYPENAME: R_0402-0OHM005OHM625MW195-2655-000-0OHM195-2655-000; DRAWING: @P2597_C02_LIB.P2597_C02(SCH_1):PAGE8; MAX_WATTAGE: 62.5mW; NV_PN: 195-2655-000; PATH: I58; PHYS_PAGE: 8; PLACEMENT_NOTE: CoLayout with L10; ROT: 0; SEC: 1; SIGNAL_MODEL: DEFAULT_RESISTOR_0.001OHM_2_1; TOL: 0.05 ohm; VER: 1; XY: (-6000,5400)
R173 = R: ASSEMBLY: USB3_TYPEA; CDS_LIB: discrete; CDS_PART_NAME: R_0402-0OHM,0.05 OHM,62.5MW,195-2655-000; CDS_PHYS_PART_NAME: R_0402-0OHM,0.05 OHM,62.5MW,195-2655-000-0OHM,195-2655-000; CDS_SEC: 1; DEVICE_TYPENAME: R_0402-0OHM005OHM625MW195-2655-000-0OHM195-2655-000; DRAWING: @P2597_C02_LIB.P2597_C02(SCH_1):PAGE8; MAX_WATTAGE: 62.5mW; NV_PN: 195-2655-000; PATH: I52; PHYS_PAGE: 8; PLACEMENT_NOTE: CoLayout with L11; ROT: 0; SEC: 1; SIGNAL_MODEL: DEFAULT_RESISTOR_0.001OHM_2_1; TOL: 0.05 ohm; VER: 1; XY: (-6900,5400)
R176 = R: ASSEMBLY: USB3_TYPEA; CDS_LIB: discrete; CDS_PART_NAME: R_0402-0OHM,0.05 OHM,62.5MW,195-2655-000; CDS_PHYS_PART_NAME: R_0402-0OHM,0.05 OHM,62.5MW,195-2655-000-0OHM,195-2655-000; CDS_SEC: 1; DEVICE_TYPENAME: R_0402-0OHM005OHM625MW195-2655-000-0OHM195-2655-000; DRAWING: @P2597_C02_LIB.P2597_C02(SCH_1):PAGE8; MAX_WATTAGE: 62.5mW; NV_PN: 195-2655-000; PATH: I55; PHYS_PAGE: 8; PLACEMENT_NOTE: CoLayout with L11; ROT: 0; SEC: 1; SIGNAL_MODEL: DEFAULT_RESISTOR_0.001OHM_2_1; TOL: 0.05 ohm; VER: 1; XY: (-6650,5100)
R181 = R: ASSEMBLY: USB3_TYPEA; CDS_LIB: discrete; CDS_PART_NAME: R_0402-0OHM,0.05 OHM,62.5MW,195-2655-000; CDS_PHYS_PART_NAME: R_0402-0OHM,0.05 OHM,62.5MW,195-2655-000-0OHM,195-2655-000; CDS_SEC: 1; DEVICE_TYPENAME: R_0402-0OHM005OHM625MW195-2655-000-0OHM195-2655-000; DRAWING: @P2597_C02_LIB.P2597_C02(SCH_1):PAGE8; MAX_WATTAGE: 62.5mW; NV_PN: 195-2655-000; PATH: I57; PHYS_PAGE: 8; PLACEMENT_NOTE: CoLayout with L12; ROT: 0; SEC: 1; SIGNAL_MODEL: DEFAULT_RESISTOR_0.001OHM_2_1; TOL: 0.05 ohm; VER: 1; XY: (-6100,5100)
R186 = R: ASSEMBLY: USB3_TYPEA; CDS_LIB: discrete; CDS_PART_NAME: R_0402-0OHM,0.05 OHM,62.5MW,195-2655-000; CDS_PHYS_PART_NAME: R_0402-0OHM,0.05 OHM,62.5MW,195-2655-000-0OHM,195-2655-000; CDS_SEC: 1; DEVICE_TYPENAME: R_0402-0OHM005OHM625MW195-2655-000-0OHM195-2655-000; DRAWING: @P2597_C02_LIB.P2597_C02(SCH_1):PAGE8; MAX_WATTAGE: 62.5mW; NV_PN: 195-2655-000; PATH: I53; PHYS_PAGE: 8; PLACEMENT_NOTE: CoLayout with L12; ROT: 0; SEC: 1; SIGNAL_MODEL: DEFAULT_RESISTOR_0.001OHM_2_1; TOL: 0.05 ohm; VER: 1; XY: (-6200,4800)
R216 = R: ASSEMBLY: USB3_TYPEA; CDS_LIB: discrete; CDS_PART_NAME: R_0402-100OHM,5 %,62.5MW,195-0484-000; CDS_PHYS_PART_NAME: R_0402-100OHM,5 %,62.5MW,195-0484-000-100OHM,195-0484-000; CDS_SEC: 1; DEVICE_TYPENAME: R_0402-100OHM5625MW195-0484-000-100OHM195-0484-000; DRAWING: @P2597_C02_LIB.P2597_C02(SCH_1):PAGE8; MAX_WATTAGE: 62.5mW; NV_PN: 195-0484-000; PATH: I194; PHYS_PAGE: 8; ROT: 6; SEC: 1; SIGNAL_MODEL: nv_res; TOL: 5%; VER: 1; XY: (-6050,6050)
R220 = R: ASSEMBLY: MICRO_USB; CDS_LIB: discrete; CDS_PART_NAME: R_0402-0OHM,0.05 OHM,62.5MW,195-2655-000; CDS_PHYS_PART_NAME: R_0402-0OHM,0.05 OHM,62.5MW,195-2655-000-0OHM,195-2655-000; CDS_SEC: 1; DEVICE_TYPENAME: R_0402-0OHM005OHM625MW195-2655-000-0OHM195-2655-000; DRAWING: @P2597_C02_LIB.P2597_C02(SCH_1):PAGE8; MAX_WATTAGE: 62.5mW; NV_PN: 195-2655-000; PATH: I199; PHYS_PAGE: 8; ROT: 0; SEC: 1; SIGNAL_MODEL: DEFAULT_RESISTOR_0.001OHM_2_1; TOL: 0.05 ohm; VER: 1; XY: (-7750,1000)
R224 = R: ASSEMBLY: MICRO_USB; CDS_LIB: discrete; CDS_PART_NAME: R_0402-0OHM,0.05 OHM,62.5MW,195-2655-000; CDS_PHYS_PART_NAME: R_0402-0OHM,0.05 OHM,62.5MW,195-2655-000-0OHM,195-2655-000; CDS_SEC: 1; DEVICE_TYPENAME: R_0402-0OHM005OHM625MW195-2655-000-0OHM195-2655-000; DRAWING: @P2597_C02_LIB.P2597_C02(SCH_1):PAGE8; MAX_WATTAGE: 62.5mW; NV_PN: 195-2655-000; PATH: I151; PHYS_PAGE: 8; PLACEMENT_NOTE: CoLayout with L13; ROT: 0; SEC: 1; SIGNAL_MODEL: nv_res; TOL: 0.05 ohm; VER: 1; XY: (-7100,1900)
R226 = R: ASSEMBLY: MICRO_USB; CDS_LIB: discrete; CDS_PART_NAME: R_0402-0OHM,0.05 OHM,62.5MW,195-2655-000; CDS_PHYS_PART_NAME: R_0402-0OHM,0.05 OHM,62.5MW,195-2655-000-0OHM,195-2655-000; CDS_SEC: 1; DEVICE_TYPENAME: R_0402-0OHM005OHM625MW195-2655-000-0OHM195-2655-000; DRAWING: @P2597_C02_LIB.P2597_C02(SCH_1):PAGE8; MAX_WATTAGE: 62.5mW; NV_PN: 195-2655-000; PATH: I153; PHYS_PAGE: 8; PLACEMENT_NOTE: CoLayout with L13; ROT: 0; SEC: 1; SIGNAL_MODEL: nv_res; TOL: 0.05 ohm; VER: 1; XY: (-7100,2200)
R227 = R: ASSEMBLY: MICRO_USB; CDS_LIB: discrete; CDS_PART_NAME: R_0402-100OHM,5 %,62.5MW,195-0484-000; CDS_PHYS_PART_NAME: R_0402-100OHM,5 %,62.5MW,195-0484-000-100OHM,195-0484-000; CDS_SEC: 1; DEVICE_TYPENAME: R_0402-100OHM5625MW195-0484-000-100OHM195-0484-000; DRAWING: @P2597_C02_LIB.P2597_C02(SCH_1):PAGE8; MAX_WATTAGE: 62.5mW; NV_PN: 195-0484-000; PATH: I177; PHYS_PAGE: 8; ROT: 0; SEC: 1; SIGNAL_MODEL: DEFAULT_RESISTOR_0.001OHM_2_1; TOL: 5%; VER: 1; XY: (-7100,2500)
R229 = R: ASSEMBLY: MICRO_USB; CDS_LIB: discrete; CDS_PART_NAME: R_0402-0OHM,0.05 OHM,62.5MW,195-2655-000; CDS_PHYS_PART_NAME: R_0402-0OHM,0.05 OHM,62.5MW,195-2655-000-0OHM,195-2655-000; CDS_SEC: 1; DEVICE_TYPENAME: R_0402-0OHM005OHM625MW195-2655-000-0OHM195-2655-000; DRAWING: @P2597_C02_LIB.P2597_C02(SCH_1):PAGE8; MAX_WATTAGE: 62.5mW; NV_PN: 195-2655-000; PATH: I180; PHYS_PAGE: 8; ROT: 0; SEC: 1; SIGNAL_MODEL: DEFAULT_RESISTOR_0.001OHM_2_1; TOL: 0.05 ohm; VER: 1; XY: (-2550,3200)
R230 = R: ASSEMBLY: MICRO_USB; CDS_LIB: discrete; CDS_PART_NAME: R_0402-0OHM,0.05 OHM,62.5MW,195-2655-000; CDS_PHYS_PART_NAME: R_0402-0OHM,0.05 OHM,62.5MW,195-2655-000-0OHM,195-2655-000; CDS_SEC: 1; DEVICE_TYPENAME: R_0402-0OHM005OHM625MW195-2655-000-0OHM195-2655-000; DRAWING: @P2597_C02_LIB.P2597_C02(SCH_1):PAGE8; MAX_WATTAGE: 62.5mW; NV_PN: 195-2655-000; PATH: I200; PHYS_PAGE: 8; ROT: 0; SEC: 1; SIGNAL_MODEL: nv_res; TOL: 0.05 ohm; VER: 1; XY: (-8750,3050)
R237 = R#1: ASSEMBLY: MICRO_USB; CDS_LIB: discrete; CDS_PART_NAME: R_0402-100K,1 %,62.5MW,195-0005-000; CDS_PHYS_PART_NAME: R_0402-100K,1 %,62.5MW,195-0005-000-100K,195-0005-000; CDS_SEC: 1; CHIPS_PART_NAME: R; DEVICE_TYPENAME: R_0402-100K1625MW195-0005-000-100K195-0005-000; DRAWING: @P2597_C02_LIB.P2597_C02(SCH_1):PAGE8; MAX_WATTAGE: 62.5mW; NV_PN: 195-0005-000; PATH: I181; PHYS_PAGE: 8; ROT: 0; SEC: 1; SIGNAL_MODEL: nv_res; TOL: 1%; VER: 2; XY: (-5650,3050)
U21 = U_POWER_SW: ASSEMBLY: USB3_TYPEA; CDS_LIB: power_supply; CDS_PART_NAME: U_POWER_SW_SOT23_5B-APL3511CBI-TRG,-9999V..9999V,-9999V..9999V,9999A,SWITCH,115-0836-000; CDS_PHYS_PART_NAME: U_POWER_SW_SOT23_5B-APL3511CBI-TRG,-9999V..9999V,-9999V..9999V,9999A,SWITCH,115-0836-000-115-0836-000; CDS_SEC: 1; DEVICE_TYPENAME: U_POWER_SW_SOT23_5B-APL3511CBI-TRG-9999V9999V-9999V9999V9999ASWITCH115-0836-000-115-0836-000; DRAWING: @P2597_C02_LIB.P2597_C02(SCH_1):PAGE8; MAX_CURRENT: 9999A; MAX_VOLTAGE: -9999V..9999V; NV_NAME: APL3511CBI-TRG; NV_PN: 115-0836-000; OUTPUT_VOLTAGE: -9999V..9999V; PACK_TYPE: SOT23_5B; PATH: I220; PHYS_PAGE: 8; ROT: 0; SEC: 1; SEC_TYPE: SOT23_5B; TYPE: Switch; VER: 7; XY: (-5200,6500)
U25 = U_POWER_SW: ASSEMBLY: MICRO_USB; CDS_LIB: power_supply; CDS_PART_NAME: U_POWER_SW_SOT23_5B-APL3511CBI-TRG,-9999V..9999V,-9999V..9999V,9999A,SWITCH,115-0836-000; CDS_PHYS_PART_NAME: U_POWER_SW_SOT23_5B-APL3511CBI-TRG,-9999V..9999V,-9999V..9999V,9999A,SWITCH,115-0836-000-115-0836-000; CDS_SEC: 1; DEVICE_TYPENAME: U_POWER_SW_SOT23_5B-APL3511CBI-TRG-9999V9999V-9999V9999V9999ASWITCH115-0836-000-115-0836-000; DRAWING: @P2597_C02_LIB.P2597_C02(SCH_1):PAGE8; MAX_CURRENT: 9999A; MAX_VOLTAGE: -9999V..9999V; NV_NAME: APL3511CBI-TRG; NV_PN: 115-0836-000; OUTPUT_VOLTAGE: -9999V..9999V; PACK_TYPE: SOT23_5B; PATH: I203; PHYS_PAGE: 8; ROT: 0; SEC: 1; SEC_TYPE: SOT23_5B; TYPE: Switch; VER: 7; XY: (-7100,3050)
C1 = C: ASSEMBLY: PEX_X4; CDS_LIB: discrete; CDS_PART_NAME: C_1206-22UF,X5R,10%,25V,039-0213-000; CDS_PHYS_PART_NAME: C_1206-22UF,X5R,10%,25V,039-0213-000-039-0213-000,22UF; CDS_SEC: 1; DEVICE_TYPENAME: C_1206-22UFX5R1025V039-0213-000-039-0213-00022UF; DRAWING: @P2597_C02_LIB.P2597_C02(SCH_1):PAGE9; MAT: X5R; MAX_VOLTAGE: 25V; NV_PN: 039-0213-000; PATH: I296; PHYS_PAGE: 9; ROT: 0; SEC: 1; SIGNAL_MODEL: DEFAULT_CAPACITOR_2.2e+07pF_2_1; TOL: 10%; VER: 1; XY: (-7750,7900)
C4 = C_POL#1: ASSEMBLY: PEX_X4; CDS_LIB: discrete; CDS_PART_NAME: C_POL_COMBI_TH_D80_D100-330UF,AL-POLYMER,20%,16V@105DEGC,0.007OHM,9.999UH,6.1A@105DEGC,100KHZ,041-0065-000; CDS_PHYS_PART_NAME: C_POL_COMBI_TH_D80_D100-330UF,AL-POLYMER,20%,16V@105DEGC,0.007OHM,9.999UH,6.1A@105DEGC,100KHZ,041-0065-000-041-0065-000,330UF; CDS_SEC: 1; CHIPS_PART_NAME: C_POL; DEVICE_TYPENAME: C_POL_COMBI_TH_D80_D100-330UFAL-POLYMER2016V105DEGC0007OHM9999UH61A105DEGC100KHZ041-0065-000-041-0065-000330UF; DRAWING: @P2597_C02_LIB.P2597_C02(SCH_1):PAGE9; ESL: 9.999uH; ESR: 0.007ohm; MAT: AL-Polymer; MAX_VOLTAGE: 16V@105degC; NV_PN: 041-0065-000; PACK_TYPE: COMBI_TH_D80_D100; PATH: I284; PHYS_PAGE: 9; RIPPLE_CURRENT: 6.1A@105degC,100KHz; ROT: 0; SEC: 1; SEC_TYPE: COMBI_TH_D80_D100; SIGNAL_MODEL: nv_capp_3p; TOL: 20%; VER: 3; XY: (-7750,8450)
C11 = C: ASSEMBLY: PEX_X4; CDS_LIB: discrete; CDS_PART_NAME: C_0402-0.1UF,X7R,10%,16V,036-0014-000; CDS_PHYS_PART_NAME: C_0402-0.1UF,X7R,10%,16V,036-0014-000-0.1UF,036-0014-000; CDS_SEC: 1; DEVICE_TYPENAME: C_0402-01UFX7R1016V036-0014-000-01UF036-0014-000; DRAWING: @P2597_C02_LIB.P2597_C02(SCH_1):PAGE9; MAT: X7R; MAX_VOLTAGE: 16V; NV_PN: 036-0014-000; PATH: I277; PHYS_PAGE: 9; ROT: 0; SEC: 1; SIGNAL_MODEL: nv_cap; TOL: 10%; VER: 1; XY: (-8350,7400)
C12 = C: ASSEMBLY: PEX_X4; CDS_LIB: discrete; CDS_PART_NAME: C_0402-0.1UF,X7R,10%,16V,036-0014-000; CDS_PHYS_PART_NAME: C_0402-0.1UF,X7R,10%,16V,036-0014-000-0.1UF,036-0014-000; CDS_SEC: 1; DEVICE_TYPENAME: C_0402-01UFX7R1016V036-0014-000-01UF036-0014-000; DRAWING: @P2597_C02_LIB.P2597_C02(SCH_1):PAGE9; MAT: X7R; MAX_VOLTAGE: 16V; NV_PN: 036-0014-000; PATH: I279; PHYS_PAGE: 9; ROT: 0; SEC: 1; SIGNAL_MODEL: nv_cap; TOL: 10%; VER: 1; XY: (-8700,7400)
C13 = C: ASSEMBLY: PEX_X4; CDS_LIB: discrete; CDS_PART_NAME: C_1206-22UF,X5R,10%,25V,039-0213-000; CDS_PHYS_PART_NAME: C_1206-22UF,X5R,10%,25V,039-0213-000-039-0213-000,22UF; CDS_SEC: 1; DEVICE_TYPENAME: C_1206-22UFX5R1025V039-0213-000-039-0213-00022UF; DRAWING: @P2597_C02_LIB.P2597_C02(SCH_1):PAGE9; MAT: X5R; MAX_VOLTAGE: 25V; NV_PN: 039-0213-000; PATH: I297; PHYS_PAGE: 9; ROT: 0; SEC: 1; SIGNAL_MODEL: DEFAULT_CAPACITOR_2.2e+07pF_2_1; TOL: 10%; VER: 1; XY: (-7400,7900)
C14 = C: ASSEMBLY: PEX_X4; CDS_LIB: discrete; CDS_PART_NAME: C_0402-0.1UF,X7R,10%,16V,036-0014-000; CDS_PHYS_PART_NAME: C_0402-0.1UF,X7R,10%,16V,036-0014-000-0.1UF,036-0014-000; CDS_SEC: 1; DEVICE_TYPENAME: C_0402-01UFX7R1016V036-0014-000-01UF036-0014-000; DRAWING: @P2597_C02_LIB.P2597_C02(SCH_1):PAGE9; MAT: X7R; MAX_VOLTAGE: 16V; NV_PN: 036-0014-000; PATH: I281; PHYS_PAGE: 9; ROT: 0; SEC: 1; SIGNAL_MODEL: nv_cap; TOL: 10%; VER: 1; XY: (-9450,7400)
C15 = C: ASSEMBLY: PEX_X4; CDS_LIB: discrete; CDS_PART_NAME: C_0402-0.1UF,X7R,10%,16V,036-0014-000; CDS_PHYS_PART_NAME: C_0402-0.1UF,X7R,10%,16V,036-0014-000-0.1UF,036-0014-000; CDS_SEC: 1; DEVICE_TYPENAME: C_0402-01UFX7R1016V036-0014-000-01UF036-0014-000; DRAWING: @P2597_C02_LIB.P2597_C02(SCH_1):PAGE9; MAT: X7R; MAX_VOLTAGE: 16V; NV_PN: 036-0014-000; PATH: I283; PHYS_PAGE: 9; ROT: 0; SEC: 1; SIGNAL_MODEL: nv_cap; TOL: 10%; VER: 1; XY: (-9900,7400)
C16 = C#1: ASSEMBLY: PEX_X4; CDS_LIB: discrete; CDS_PART_NAME: C_0402-0.1UF,X7R,10%,16V,036-0014-000; CDS_PHYS_PART_NAME: C_0402-0.1UF,X7R,10%,16V,036-0014-000-0.1UF,036-0014-000; CDS_SEC: 1; CHIPS_PART_NAME: C; DEVICE_TYPENAME: C_0402-01UFX7R1016V036-0014-000-01UF036-0014-000; DRAWING: @P2597_C02_LIB.P2597_C02(SCH_1):PAGE9; MAT: X7R; MAX_VOLTAGE: 16V; NV_PN: 036-0014-000; PATH: I260; PHYS_PAGE: 9; ROT: 0; SEC: 1; SIGNAL_MODEL: nv_cap; TOL: 10%; VER: 2; XY: (-7350,2800)
C17 = C#1: ASSEMBLY: PEX_X4; CDS_LIB: discrete; CDS_PART_NAME: C_0402-0.1UF,X7R,10%,16V,036-0014-000; CDS_PHYS_PART_NAME: C_0402-0.1UF,X7R,10%,16V,036-0014-000-0.1UF,036-0014-000; CDS_SEC: 1; CHIPS_PART_NAME: C; DEVICE_TYPENAME: C_0402-01UFX7R1016V036-0014-000-01UF036-0014-000; DRAWING: @P2597_C02_LIB.P2597_C02(SCH_1):PAGE9; MAT: X7R; MAX_VOLTAGE: 16V; NV_PN: 036-0014-000; PATH: I259; PHYS_PAGE: 9; ROT: 0; SEC: 1; SIGNAL_MODEL: nv_cap; TOL: 10%; VER: 2; XY: (-7350,2950)
C18 = C#1: ASSEMBLY: PEX_X4; CDS_LIB: discrete; CDS_PART_NAME: C_0402-0.1UF,X7R,10%,16V,036-0014-000; CDS_PHYS_PART_NAME: C_0402-0.1UF,X7R,10%,16V,036-0014-000-0.1UF,036-0014-000; CDS_SEC: 1; CHIPS_PART_NAME: C; DEVICE_TYPENAME: C_0402-01UFX7R1016V036-0014-000-01UF036-0014-000; DRAWING: @P2597_C02_LIB.P2597_C02(SCH_1):PAGE9; MAT: X7R; MAX_VOLTAGE: 16V; NV_PN: 036-0014-000; PATH: I264; PHYS_PAGE: 9; ROT: 0; SEC: 1; SIGNAL_MODEL: nv_cap; TOL: 10%; VER: 2; XY: (-7350,3100)
C19 = C#1: ASSEMBLY: PEX_X4; CDS_LIB: discrete; CDS_PART_NAME: C_0402-0.1UF,X7R,10%,16V,036-0014-000; CDS_PHYS_PART_NAME: C_0402-0.1UF,X7R,10%,16V,036-0014-000-0.1UF,036-0014-000; CDS_SEC: 1; CHIPS_PART_NAME: C; DEVICE_TYPENAME: C_0402-01UFX7R1016V036-0014-000-01UF036-0014-000; DRAWING: @P2597_C02_LIB.P2597_C02(SCH_1):PAGE9; MAT: X7R; MAX_VOLTAGE: 16V; NV_PN: 036-0014-000; PATH: I263; PHYS_PAGE: 9; ROT: 0; SEC: 1; SIGNAL_MODEL: nv_cap; TOL: 10%; VER: 2; XY: (-7350,3250)
C20 = C#1: ASSEMBLY: PEX_X4; CDS_LIB: discrete; CDS_PART_NAME: C_0402-0.1UF,X7R,10%,16V,036-0014-000; CDS_PHYS_PART_NAME: C_0402-0.1UF,X7R,10%,16V,036-0014-000-0.1UF,036-0014-000; CDS_SEC: 1; CHIPS_PART_NAME: C; DEVICE_TYPENAME: C_0402-01UFX7R1016V036-0014-000-01UF036-0014-000; DRAWING: @P2597_C02_LIB.P2597_C02(SCH_1):PAGE9; MAT: X7R; MAX_VOLTAGE: 16V; NV_PN: 036-0014-000; PATH: I265; PHYS_PAGE: 9; ROT: 0; SEC: 1; SIGNAL_MODEL: nv_cap; TOL: 10%; VER: 2; XY: (-7350,3400)
C21 = C#1: ASSEMBLY: PEX_X4; CDS_LIB: discrete; CDS_PART_NAME: C_0402-0.1UF,X7R,10%,16V,036-0014-000; CDS_PHYS_PART_NAME: C_0402-0.1UF,X7R,10%,16V,036-0014-000-0.1UF,036-0014-000; CDS_SEC: 1; CHIPS_PART_NAME: C; DEVICE_TYPENAME: C_0402-01UFX7R1016V036-0014-000-01UF036-0014-000; DRAWING: @P2597_C02_LIB.P2597_C02(SCH_1):PAGE9; MAT: X7R; MAX_VOLTAGE: 16V; NV_PN: 036-0014-000; PATH: I266; PHYS_PAGE: 9; ROT: 0; SEC: 1; SIGNAL_MODEL: nv_cap; TOL: 10%; VER: 2; XY: (-7350,3550)
C22 = C#1: ASSEMBLY: PEX_X4; CDS_LIB: discrete; CDS_PART_NAME: C_0402-0.1UF,X7R,10%,16V,036-0014-000; CDS_PHYS_PART_NAME: C_0402-0.1UF,X7R,10%,16V,036-0014-000-0.1UF,036-0014-000; CDS_SEC: 1; CHIPS_PART_NAME: C; DEVICE_TYPENAME: C_0402-01UFX7R1016V036-0014-000-01UF036-0014-000; DRAWING: @P2597_C02_LIB.P2597_C02(SCH_1):PAGE9; MAT: X7R; MAX_VOLTAGE: 16V; NV_PN: 036-0014-000; PATH: I267; PHYS_PAGE: 9; ROT: 0; SEC: 1; SIGNAL_MODEL: nv_cap; TOL: 10%; VER: 2; XY: (-7350,3700)
C23 = C#1: ASSEMBLY: PEX_X4; CDS_LIB: discrete; CDS_PART_NAME: C_0402-0.1UF,X7R,10%,16V,036-0014-000; CDS_PHYS_PART_NAME: C_0402-0.1UF,X7R,10%,16V,036-0014-000-0.1UF,036-0014-000; CDS_SEC: 1; CHIPS_PART_NAME: C; DEVICE_TYPENAME: C_0402-01UFX7R1016V036-0014-000-01UF036-0014-000; DRAWING: @P2597_C02_LIB.P2597_C02(SCH_1):PAGE9; MAT: X7R; MAX_VOLTAGE: 16V; NV_PN: 036-0014-000; PATH: I268; PHYS_PAGE: 9; ROT: 0; SEC: 1; SIGNAL_MODEL: nv_cap; TOL: 10%; VER: 2; XY: (-7350,3850)
C40 = C_POL: ASSEMBLY: PEX_X4; CDS_LIB: discrete; CDS_PART_NAME: C_POL_SMD_D60-330UF,AL-POLYMER,20%,6.3V@105DEGC,0.01OHM,9.999UH,3.9A@105DEGC,100KHZ,042-0138-000; CDS_PHYS_PART_NAME: C_POL_SMD_D60-330UF,AL-POLYMER,20%,6.3V@105DEGC,0.01OHM,9.999UH,3.9A@105DEGC,100KHZ,042-0138-000-042-0138-000,330UF; CDS_SEC: 1; DEVICE_TYPENAME: C_POL_SMD_D60-330UFAL-POLYMER2063V105DEGC001OHM9999UH39A105DEGC100KHZ042-0138-000-042-0138-000330UF; DRAWING: @P2597_C02_LIB.P2597_C02(SCH_1):PAGE9; ESL: 9.999uH; ESR: 0.01ohm; MAT: AL-Polymer; MAX_VOLTAGE: 6.3V@105degC; NV_PN: 042-0138-000; PACK_TYPE: SMD_D60; PATH: I285; PHYS_PAGE: 9; RIPPLE_CURRENT: 3.9A@105degC,100KHz; ROT: 0; SEC: 1; SEC_TYPE: SMD_D60; SIGNAL_MODEL: nv_capp; TOL: 20%; VER: 1; XY: (-9750,8350)
CR6 = LED: ASSEMBLY: PEX_X4; CDS_LIB: discrete; CDS_PART_NAME: LED_0402-LTST-C281KRKT-5A,5V,80MA,2.3V,30MA,RED,092-0090-000; CDS_PHYS_PART_NAME: LED_0402-LTST-C281KRKT-5A,5V,80MA,2.3V,30MA,RED,092-0090-000-092-0090-000; CDS_SEC: 1; CONTINUOUS_CURRENT: 30mA; DEVICE_TYPENAME: LED_0402-LTST-C281KRKT-5A5V80MA23V30MARED092-0090-000-092-0090-000; DRAWING: @P2597_C02_LIB.P2597_C02(SCH_1):PAGE9; FORWARD_VOLTAGE: 2.3V; MAX_CURRENT: 80mA; MAX_VOLTAGE: 5V; NV_COLOR: Red; NV_NAME: LTST-C281KRKT-5A; NV_PN: 092-0090-000; PACK_TYPE: 402; PATH: I311; PHYS_PAGE: 9; ROT: 0; SEC: 1; VER: 1; XY: (-8350,8000)
D19 = D_ESD#1: ASSEMBLY: PEX_X4; BREAKDOWN_VOLTAGE_MIN_TYP: 6.2V; CAPACITANCE_MAX_TYP: 65pF; CDS_LIB: discrete; CDS_PART_NAME: D_ESD_SOD923-ESD9X5.0ST5G,1 LINE,UNI-DIRECTIONAL,5V,1UA,6.2V,12.3V@8.7A,65PF,090-0134-000; CDS_PHYS_PART_NAME: D_ESD_SOD923-ESD9X5.0ST5G,1 LINE,UNI-DIRECTIONAL,5V,1UA,6.2V,12.3V@8.7A,65PF,090-0134-000-090-0134-000; CDS_SEC: 1; CLAMPING_VOLTAGE: 12.3V@8.7A; CONFIGURATION: 1 Line; CONTINUOUS_CURRENT: -1A; DEVICE_TYPENAME: D_ESD_SOD923-ESD9X50ST5G1LINEUNI-DIRECTIONAL5V1UA62V123V87A65PF090-0134-000-090-0134-000; DRAWING: @P2597_C02_LIB.P2597_C02(SCH_1):PAGE9; FORWARD_VOLTAGE: [ ]@-9.999A; MAX_CURRENT: [ ]; MAX_REVERSE_LEAKAGE_CURRENT: 1uA; MAX_REVERSE_VOLTAGE: 5V; MAX_VOLTAGE: 5V; NV_NAME: ESD9X5.0ST5G; NV_PN: 090-0134-000; PACK_TYPE: SOD923; PATH: I313; PHYS_PAGE: 9; POLARITY: Uni-Directional; ROT: 6; SEC: 1; SEC_TYPE: SOD923; VER: 5; XY: (-5450,7050)
D20 = D_ESD#1: ASSEMBLY: PEX_X4; BREAKDOWN_VOLTAGE_MIN_TYP: 6.2V; CAPACITANCE_MAX_TYP: 65pF; CDS_LIB: discrete; CDS_PART_NAME: D_ESD_SOD923-ESD9X5.0ST5G,1 LINE,UNI-DIRECTIONAL,5V,1UA,6.2V,12.3V@8.7A,65PF,090-0134-000; CDS_PHYS_PART_NAME: D_ESD_SOD923-ESD9X5.0ST5G,1 LINE,UNI-DIRECTIONAL,5V,1UA,6.2V,12.3V@8.7A,65PF,090-0134-000-090-0134-000; CDS_SEC: 1; CLAMPING_VOLTAGE: 12.3V@8.7A; CONFIGURATION: 1 Line; CONTINUOUS_CURRENT: -1A; DEVICE_TYPENAME: D_ESD_SOD923-ESD9X50ST5G1LINEUNI-DIRECTIONAL5V1UA62V123V87A65PF090-0134-000-090-0134-000; DRAWING: @P2597_C02_LIB.P2597_C02(SCH_1):PAGE9; FORWARD_VOLTAGE: [ ]@-9.999A; MAX_CURRENT: [ ]; MAX_REVERSE_LEAKAGE_CURRENT: 1uA; MAX_REVERSE_VOLTAGE: 5V; MAX_VOLTAGE: 5V; NV_NAME: ESD9X5.0ST5G; NV_PN: 090-0134-000; PACK_TYPE: SOD923; PATH: I314; PHYS_PAGE: 9; POLARITY: Uni-Directional; ROT: 6; SEC: 1; SEC_TYPE: SOD923; VER: 5; XY: (-5000,7050)
D21 = D_ESD#1: ASSEMBLY: PEX_X4; BREAKDOWN_VOLTAGE_MIN_TYP: 6.2V; CAPACITANCE_MAX_TYP: 65pF; CDS_LIB: discrete; CDS_PART_NAME: D_ESD_SOD923-ESD9X5.0ST5G,1 LINE,UNI-DIRECTIONAL,5V,1UA,6.2V,12.3V@8.7A,65PF,090-0134-000; CDS_PHYS_PART_NAME: D_ESD_SOD923-ESD9X5.0ST5G,1 LINE,UNI-DIRECTIONAL,5V,1UA,6.2V,12.3V@8.7A,65PF,090-0134-000-090-0134-000; CDS_SEC: 1; CLAMPING_VOLTAGE: 12.3V@8.7A; CONFIGURATION: 1 Line; CONTINUOUS_CURRENT: -1A; DEVICE_TYPENAME: D_ESD_SOD923-ESD9X50ST5G1LINEUNI-DIRECTIONAL5V1UA62V123V87A65PF090-0134-000-090-0134-000; DRAWING: @P2597_C02_LIB.P2597_C02(SCH_1):PAGE9; FORWARD_VOLTAGE: [ ]@-9.999A; MAX_CURRENT: [ ]; MAX_REVERSE_LEAKAGE_CURRENT: 1uA; MAX_REVERSE_VOLTAGE: 5V; MAX_VOLTAGE: 5V; NV_NAME: ESD9X5.0ST5G; NV_PN: 090-0134-000; PACK_TYPE: SOD923; PATH: I316; PHYS_PAGE: 9; POLARITY: Uni-Directional; ROT: 0; SEC: 1; SEC_TYPE: SOD923; VER: 5; XY: (-8800,6100)
J2 = CON_PCI_EXPRESS: ANGLE: 0; ASSEMBLY: PEX_X4; CDS_LIB: electro_mechanic; CDS_PART_NAME: CON_PCI_EXPRESS_PHY-X4-CON_PCIEXP_X4_MB,FEMALE,1MM,0,YES,YES,NO,NO,NO,50V,1.1A,065-0362-000; CDS_PHYS_PART_NAME: CON_PCI_EXPRESS_PHY-X4-CON_PCIEXP_X4_MB,FEMALE,1MM,0,YES,YES,NO,NO,NO,50V,1.1A,065-0362-000-065-0362-000; CDS_SEC: 1; DEVICE_TYPENAME: CON_PCI_EXPRESS_PHY-X4-CON_PCIEXP_X4_MBFEMALE1MM0YESYESNONONO50V11A065-0362-000-065-0362-000; DRAWING: @P2597_C02_LIB.P2597_C02(SCH_1):PAGE9; EMI_GROUND_TAB: NO; GENDER: FEMALE; LATCHING: NO; MAX_CURRENT: 1.1A; MAX_VOLTAGE: 50V; NV_NAME: CON_PCIEXP_X4_MB; NV_PN: 065-0362-000; PACK_TYPE: PHY-X4; PATH: I246; PHYS_PAGE: 9; PITCH: 1MM; REFLOW: YES; ROT: 0; SEC: 1; SEC_TYPE: PHY-X4; SHIELDED: NO; SHROUDED: YES; VER: 3; XY: (-7400,6000)
R3 = R#1: ASSEMBLY: PEX_X4; CDS_LIB: discrete; CDS_PART_NAME: R_0402-10K,5 %,62.5MW,195-0486-000; CDS_PHYS_PART_NAME: R_0402-10K,5 %,62.5MW,195-0486-000-10K,195-0486-000; CDS_SEC: 1; CHIPS_PART_NAME: R; DEVICE_TYPENAME: R_0402-10K5625MW195-0486-000-10K195-0486-000; DRAWING: @P2597_C02_LIB.P2597_C02(SCH_1):PAGE9; MAX_WATTAGE: 62.5mW; NV_PN: 195-0486-000; PATH: I241; PHYS_PAGE: 9; ROT: 0; SEC: 1; SIGNAL_MODEL: DEFAULT_RESISTOR_10000OHM_2_1; TOL: 5%; VER: 2; XY: (-6150,7000)
R6 = R: ASSEMBLY: PEX_X4; CDS_LIB: discrete; CDS_PART_NAME: R_0402-0OHM,0.05 OHM,62.5MW,195-2655-000; CDS_PHYS_PART_NAME: R_0402-0OHM,0.05 OHM,62.5MW,195-2655-000-0OHM,195-2655-000; CDS_SEC: 1; DEVICE_TYPENAME: R_0402-0OHM005OHM625MW195-2655-000-0OHM195-2655-000; DRAWING: @P2597_C02_LIB.P2597_C02(SCH_1):PAGE9; MAX_WATTAGE: 62.5mW; NV_PN: 195-2655-000; PATH: I295; PHYS_PAGE: 9; ROT: 0; SEC: 1; SIGNAL_MODEL: nv_res; TOL: 0.05 ohm; VER: 1; XY: (-9250,6400)
R7 = R#1: ASSEMBLY: PEX_X4; CDS_LIB: discrete; CDS_PART_NAME: R_0402-100K,1 %,62.5MW,195-0005-000; CDS_PHYS_PART_NAME: R_0402-100K,1 %,62.5MW,195-0005-000-100K,195-0005-000; CDS_SEC: 1; CHIPS_PART_NAME: R; DEVICE_TYPENAME: R_0402-100K1625MW195-0005-000-100K195-0005-000; DRAWING: @P2597_C02_LIB.P2597_C02(SCH_1):PAGE9; MAX_WATTAGE: 62.5mW; NV_PN: 195-0005-000; PATH: I203; PHYS_PAGE: 9; ROT: 2; SEC: 1; SIGNAL_MODEL: nv_res; SKU: NO STUFF; TOL: 1%; VER: 2; XY: (-9450,6800)
R349 = R#1: ASSEMBLY: PEX_X4; CDS_LIB: discrete; CDS_PART_NAME: R_0402-1.8K,5 %,62.5MW,195-0528-000; CDS_PHYS_PART_NAME: R_0402-1.8K,5 %,62.5MW,195-0528-000-1.8K,195-0528-000; CDS_SEC: 1; CHIPS_PART_NAME: R; DEVICE_TYPENAME: R_0402-18K5625MW195-0528-000-18K195-0528-000; DRAWING: @P2597_C02_LIB.P2597_C02(SCH_1):PAGE9; MAX_WATTAGE: 62.5mW; NV_PN: 195-0528-000; PATH: I312; PHYS_PAGE: 9; ROT: 2; SEC: 1; SIGNAL_MODEL: nv_res; TOL: 5%; VER: 2; XY: (-8350,8300)

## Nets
GND: C1.2 C4.2 C4.3 C11.2 C12.2 C13.2 C14.2 C15.2 C40.2 C113.2 C115.2 C121.2 C122.2 C127.2 C131.2 C134.2 C145.2 C147.2 C150.2 C151.2 C152.2 C153.2 CR6.1(C) D8.3(GND1) D9.3(GND1) D10.3(GND1) D11.2 D19.2(2A) D20.2(2A) D21.2(2A) J2.A1(PRSNT1*) J2.A4(GND_02) J2.A12(GND_04) J2.A15(GND_06) J2.A18(GND_09) J2.A20(GND_10) J2.A23(GND_13) J2.A24(GND_14) J2.A27(GND_17) J2.A28(GND_18) J2.A31(GND_20) J2.B4(GND_01) J2.B7(GND_03) J2.B13(GND_05) J2.B16(GND_07) J2.B18(GND_08) J2.B21(GND_11) J2.B22(GND_12) J2.B25(GND_15) J2.B26(GND_16) J2.B29(GND_19) J2.B32(GND_21) J19.4(GND1) J19.7(GND2) J19.10(MT1) J19.11(MT2) J28.5(GND) J28.6(SH1) J28.7(SH2) J28.8(SH3) J28.9(SH4) J28.10(MT1) J28.11(MT2) R3.2 R237.2 U21.2(GND) U25.2(GND) ; also on sheet 1 2 3 4 5 6 7 9 10 11 12 13 14 15 16 17 18 19 20 21 22 23 24 30
VDD_3V3_SLP: C14.1 C15.1 C40.1 J2.A9(3V3_02) J2.A10(3V3_03) J2.B8(3V3_01) ; also on sheet 4 5 11 16 17 20 21 22
VDD_3V3_SYS: J2.B10(3V3AUX) R7.1 ; also on sheet 1 2 3 4 5 6 12 13 17 18 19 23 24
VDD_5V0_IO_SYS: C127.1 C131.1 C150.1 C152.1 U21.5(IN) U25.5(IN) ; also on sheet 4 5 6 9 11 12 16 17 18 20 22 30
VDD_12V_SLP: C1.1 C4.1 C11.1 C12.1 C13.1 J2.A2(12V_03) J2.A3(12V_04) J2.B1(12V_01) J2.B2(12V_02) J2.B3(RSVD[0]) R349.1 ; also on sheet 11 12 22
VDD_VBUS: R229.2 ; also on sheet 30
VDD_VBUS_CONN: C151.1 C153.1 LB11.1 R237.1 U25.1(OUT)
VDD_VBUS_CONN_L: C145.1 C147.1 D11.1 J28.1(VBUS) LB11.2 R229.1
I2C_GP0_SCL_3V3_LVL: J2.B5(SMCLK) ; also on sheet 18 24
I2C_GP0_SDA_3V3_LVL: J2.B6(SMDAT) ; also on sheet 18 24
PCIE0_12V_LED: CR6.2(A) R349.2
PCIE0_L0_CLKREQ: R6.1 ; also on sheet 28
PCIE0_L0_CLKREQ_R: D21.1(1C) J2.B12(RSVD[1]) R6.2
PCIE0_L0_RST: D19.1(1C) J2.A11(PERST*) ; also on sheet 28
PCIE0_PRSNT_L: J2.B17(PRSNT2X1*) J2.B31(PRSNT2X4*) R7.2
PCIE_JTAG_TRST_PD: J2.B9(TRST*) R3.1
PCIE_WAKE_L: D20.1(1C) J2.B11(WAKE*) ; also on sheet 24 28
PEX_CLK0_N: J2.A14(REFCLKN*) ; also on sheet 28
PEX_CLK0_P: J2.A13(REFCLKP) ; also on sheet 28
PEX_RX1_N: J2.A30(PERN3*) ; also on sheet 28
PEX_RX1_P: J2.A29(PERP3) ; also on sheet 28
PEX_RX2_N: J2.A26(PERN2*) ; also on sheet 28
PEX_RX2_P: J2.A25(PERP2) ; also on sheet 28
PEX_RX3_N: J2.A22(PERN1*) ; also on sheet 28
PEX_RX3_P: J2.A21(PERP1) ; also on sheet 28
PEX_RX4_N: J2.A17(PERN0*) ; also on sheet 28
PEX_RX4_P: J2.A16(PERP0) ; also on sheet 28
PEX_TX1_C_N: C22.2 J2.B28(PETN3*)
PEX_TX1_C_P: C23.2 J2.B27(PETP3)
PEX_TX1_N: C22.1 ; also on sheet 28
PEX_TX1_P: C23.1 ; also on sheet 28
PEX_TX2_C_N: C20.2 J2.B24(PETN2*)
PEX_TX2_C_P: C21.2 J2.B23(PETP2)
PEX_TX2_N: C20.1 ; also on sheet 28
PEX_TX2_P: C21.1 ; also on sheet 28
PEX_TX3_C_N: C18.2 J2.B20(PETN1*)
PEX_TX3_C_P: C19.2 J2.B19(PETP1)
PEX_TX3_N: C18.1 ; also on sheet 28
PEX_TX3_P: C19.1 ; also on sheet 28
PEX_TX4_C_N: C16.2 J2.B15(PETN0*)
PEX_TX4_C_P: C17.2 J2.B14(PETP0)
PEX_TX4_N: C16.1 ; also on sheet 28
PEX_TX4_P: C17.1 ; also on sheet 28
SNN_PCIE_JTAG_TCLK: J2.A5(TCLK)
SNN_PCIE_JTAG_TDI: J2.A6(TDI)
SNN_PCIE_JTAG_TDO: J2.A7(TDO)
SNN_PCIE_JTAG_TMS: J2.A8(TMS)
SNN_PCIE_RSVD1: J2.A19(RSVD[2])
SNN_PCIE_RSVD2: J2.B30(RSVD[3])
SNN_PCIE_RSVD3: J2.A32(RSVD[4])
SNN_USB2_ESD_NC1: D8.4(3A)
SNN_USB2_ESD_NC2: D8.5(4A)
SNN_USB2_ESD_NC3: D8.7(3B)
SNN_USB2_ESD_NC4: D8.6(4B)
SNN_USB_ESD_NC1: D10.1(1A)
SNN_USB_ESD_NC2: D10.10(1B)
USB0_D_N: D10.5(4A) D10.6(4B) J28.2(DN) L13.3 R226.2
USB0_D_P: D10.4(3A) D10.7(3B) J28.3(DP) L13.4 R224.2
USB0_ID_IO_CONN: R220.1 ; also on sheet 30
USB0_ID_IO_CONN_D: C134.1 D10.2(2A) D10.9(2B) J28.4(ID) R220.2
USB0_IO_CONN_D_N: L13.2 R226.1 ; also on sheet 30
USB0_IO_CONN_D_P: L13.1 R224.1 ; also on sheet 30
USB0_OC*: R227.2 U25.3(OC*)
USB0_VBUS_EN: R227.1 R230.2 U25.4(EN)
USB1_D_N: L10.1 R167.1 ; also on sheet 28
USB1_D_P: L10.2 R169.1 ; also on sheet 28
USB1_F_D_N: D8.2(2A) D8.9(2B) J19.2(DN) L10.4 R167.2
USB1_F_D_P: D8.1(1A) D8.10(1B) J19.3(DP) L10.3 R169.2
USB3_RX1_F_N: D9.1(1A) D9.10(1B) J19.5(SSRXN) L11.3(P3) R173.2
USB3_RX1_F_P: D9.2(2A) D9.9(2B) J19.6(SSRXP) L11.2(P2) R176.2
USB3_RX1_N: L11.4(P4) R173.1 ; also on sheet 28
USB3_RX1_P: L11.1(P1) R176.1 ; also on sheet 28
USB3_TX1_C_N: D9.4(3A) D9.7(3B) J19.8(SSTXN) L12.3(P3) R181.2
USB3_TX1_C_P: D9.5(4A) D9.6(4B) J19.9(SSTXP) L12.2(P2) R186.2
USB3_TX1_F_N: C105.2 L12.4(P4) R181.1
USB3_TX1_F_P: C109.2 L12.1(P1) R186.1
USB3_TX1_N: C105.1 ; also on sheet 28
USB3_TX1_P: C109.1 ; also on sheet 28
USB_VBUS_EN0: R230.1 ; also on sheet 30
USB_VBUS_EN1: R216.1 U21.4(EN) ; also on sheet 28
USB_VBUS_J38: C115.1 J19.1(VBUS) LB10.2
USB_VBUS_J38_FB: C113.1 C121.1 C122.1 LB10.1 U21.1(OUT)
USB_VBUS_OC0: R216.2 U21.3(OC*)

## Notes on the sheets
sheet 25
- A
- B
- C
- D
- E
- F
- G
- H
- 1
- 1
- 2
- 2
- NS
- 3
- 3
- 4
- 4
- 5
- 5
- NVIDIA CORPORATION
- 2701 SAN TOMAS EXPRESSWAY
- ASSEMBLY
- <ASSEMBLY_DESCRIPTION>
- SANTA CLARA, CA 95050, USA
- PAGE DETAIL
- PCIe x4 Connector
- NV_PN
- 600-82597-BASE-900
- ALL NVIDIA DESIGN SPECIFICATIONS, REFERENCE SPECIFICATIONS, REFERENCE BOARDS, FILES, DRAWINGS, DIAGNOSTICS, LISTS AND OTHER DOCUMENTS OR INFORMATION (TOGETHER AND SEPARATELY, 'MATERIALS') ARE BEING PROVIDED 'AS IS'. THE MATERIALS MAY
- CONTAIN KNOWN AND UNKNOWN VIOLATIONS OR DEVIATIONS OF INDUSTRY STANDARDS AND SPECIFICATIONS. NVIDIA MAKES NO WARRANTIES, EXPRESSED, IMPLIED, STATUTORY OR OTHERWISE WITH RESPECT TO THE MATERIALS OR OTHERWISE, AND EXPRESSLY DISCLAIMS ALL
- PCB REV
- P2597-C02
- PAGE
- 9 OF 34
- IMPLIED WARRANTIES INCLUDING, WITHOUT LIMITATION, THE WARRANTIES OF DESIGN, OF NONINFRINGEMENT, MERCHANTABILITY OR FITNESS FOR A PARTICULAR PURPOSE, OR ARISING FROM A COURSE OF DEALING, TRADE USAGE, TRADE PRACTICE, OR INDUSTRY STANDARDS.
- BOM REV
- A
- DATE
- 23-OCT-2017
- A
- B
- C
- D
- E
- F
- G
- H
sheet 26
- A
- B
- C
- D
- E
- F
- G
- H
- USB 3.0 TYPE A CONNECTOR
- 1
- 1
- Co-locate Resistors to avoid stubs
- PCB CO-LAYOUT
- SIGNAL NAME
- IMPEDANCE
- 2
- 2
- USB3.0 CONNECTOR
- MICRO AB USB 2.0 CONNECTOR
- 3
- 3
- 4
- 4
- PCB CO-LAYOUT
- 5
- 5
- NVIDIA CORPORATION
- 2701 SAN TOMAS EXPRESSWAY
- ASSEMBLY
- <ASSEMBLY_DESCRIPTION>
- SANTA CLARA, CA 95050, USA
- PAGE DETAIL
- USB3.0 type A and USB2.0 micro
- NV_PN
- 600-82597-BASE-900
- ALL NVIDIA DESIGN SPECIFICATIONS, REFERENCE SPECIFICATIONS, REFERENCE BOARDS, FILES, DRAWINGS, DIAGNOSTICS, LISTS AND OTHER DOCUMENTS OR INFORMATION (TOGETHER AND SEPARATELY, 'MATERIALS') ARE BEING PROVIDED 'AS IS'. THE MATERIALS MAY
- CONTAIN KNOWN AND UNKNOWN VIOLATIONS OR DEVIATIONS OF INDUSTRY STANDARDS AND SPECIFICATIONS. NVIDIA MAKES NO WARRANTIES, EXPRESSED, IMPLIED, STATUTORY OR OTHERWISE WITH RESPECT TO THE MATERIALS OR OTHERWISE, AND EXPRESSLY DISCLAIMS ALL
- PCB REV
- P2597-C02
- PAGE
- 8 OF 34
- IMPLIED WARRANTIES INCLUDING, WITHOUT LIMITATION, THE WARRANTIES OF DESIGN, OF NONINFRINGEMENT, MERCHANTABILITY OR FITNESS FOR A PARTICULAR PURPOSE, OR ARISING FROM A COURSE OF DEALING, TRADE USAGE, TRADE PRACTICE, OR INDUSTRY STANDARDS.
- BOM REV
- A
- DATE
- 23-OCT-2017
- A
- B
- C
- D
- E
- F
- G
- H
sheet 27
- A
- B
- C
- D
- E
- F
- G
- H
- BLANK
- 1
- 1
- 2
- 2
- 3
- 3
- 4
- 4
- 5
- 5
- NVIDIA CORPORATION
- 2701 SAN TOMAS EXPRESSWAY
- ASSEMBLY
- <ASSEMBLY_DESCRIPTION>
- SANTA CLARA, CA 95050, USA
- PAGE DETAIL
- BLANK
- NV_PN
- 600-82597-BASE-900
- ALL NVIDIA DESIGN SPECIFICATIONS, REFERENCE SPECIFICATIONS, REFERENCE BOARDS, FILES, DRAWINGS, DIAGNOSTICS, LISTS AND OTHER DOCUMENTS OR INFORMATION (TOGETHER AND SEPARATELY, 'MATERIALS') ARE BEING PROVIDED 'AS IS'. THE MATERIALS MAY
- CONTAIN KNOWN AND UNKNOWN VIOLATIONS OR DEVIATIONS OF INDUSTRY STANDARDS AND SPECIFICATIONS. NVIDIA MAKES NO WARRANTIES, EXPRESSED, IMPLIED, STATUTORY OR OTHERWISE WITH RESPECT TO THE MATERIALS OR OTHERWISE, AND EXPRESSLY DISCLAIMS ALL
- PCB REV
- P2597-C02
- PAGE
- 7 OF 34
- .
- IMPLIED WARRANTIES INCLUDING, WITHOUT LIMITATION, THE WARRANTIES OF DESIGN, OF NONINFRINGEMENT, MERCHANTABILITY OR FITNESS FOR A PARTICULAR PURPOSE, OR ARISING FROM A COURSE OF DEALING, TRADE USAGE, TRADE PRACTICE, OR INDUSTRY STANDARDS.
- BOM REV
- A
- DATE
- 23-OCT-2017
- A
- B
- C
- D
- E
- F
- G
- H
